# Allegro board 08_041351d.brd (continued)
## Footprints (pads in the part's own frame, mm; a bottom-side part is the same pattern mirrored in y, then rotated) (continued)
C0201
  rect 0.305x0.406 smd: 1(-0.318,0) 2(0.318,0)
C0402
  rect 0.889x0.813 smd: 1(-0.635,0) 2(0.635,0)
C0402H22
  rect 0.889x0.813 smd: 1(-0.635,0) 2(0.635,0)
C0603
  rect 1.092x1.194 smd: 1(-0.851,0) 2(0.851,0)
C0805
  rect 1.295x1.6 smd: 1(-0.953,0) 2(0.953,0)
C0805H53
  rect 1.295x1.6 smd: 1(-0.953,0) 2(0.953,0)
C0805H60
  rect 1.295x1.6 smd: 1(-0.953,0) 2(0.953,0)
C1206H71
  rect 1.6x2.007 smd: 1(-1.397,0) 2(1.397,0)
CNFCI61082-101400
  round 2.21 hole 1.194 unplated: (-22.1,0)
  round 1.905 hole 0.787 unplated: (22.1,0)
  rect 0.508x2.007 smd: 1(-19.6,-2.2) 2(-19.6,2.2) 3(-18.8,-2.2) 4(-18.8,2.2) 5(-18,-2.2) 6(-18,2.2) 7(-17.2,-2.2) 8(-17.2,2.2) 9(-16.4,-2.2) 10(-16.4,2.2) 11(-15.6,-2.2) 12(-15.6,2.2) 13(-14.8,-2.2) 14(-14.8,2.2) 15(-14,-2.2) 16(-14,2.2) 17(-13.2,-2.2) 18(-13.2,2.2) 19(-12.4,-2.2) 20(-12.4,2.2) 21(-11.6,-2.2) 22(-11.6,2.2) 23(-10.8,-2.2) 24(-10.8,2.2) 25(-10,-2.2) 26(-10,2.2) 27(-9.2,-2.2) 28(-9.2,2.2) 29(-8.4,-2.2) 30(-8.4,2.2) 31(-7.6,-2.2) 32(-7.6,2.2) 33(-6.8,-2.2) 34(-6.8,2.2) 35(-6,-2.2) 36(-6,2.2) 37(-5.2,-2.2) 38(-5.2,2.2) 39(-4.4,-2.2) 40(-4.4,2.2) 41(-3.6,-2.2) 42(-3.6,2.2) 43(-2.8,-2.2) 44(-2.8,2.2) 45(-2,-2.2) 46(-2,2.2) 47(-1.2,-2.2) 48(-1.2,2.2) 49(-0.4,-2.2) 50(-0.4,2.2) 51(0.4,-2.2) 52(0.4,2.2) 53(1.2,-2.2) 54(1.2,2.2) 55(2,-2.2) 56(2,2.2) 57(2.8,-2.2) 58(2.8,2.2) 59(3.6,-2.2) 60(3.6,2.2) 61(4.4,-2.2) 62(4.4,2.2) 63(5.2,-2.2) 64(5.2,2.2) 65(6,-2.2) 66(6,2.2) 67(6.8,-2.2) 68(6.8,2.2) 69(7.6,-2.2) 70(7.6,2.2) 71(8.4,-2.2) 72(8.4,2.2) 73(9.2,-2.2) 74(9.2,2.2) 75(10,-2.2) 76(10,2.2) 77(10.8,-2.2) 78(10.8,2.2) 79(11.6,-2.2) 80(11.6,2.2) 81(12.4,-2.2) 82(12.4,2.2) 83(13.2,-2.2) 84(13.2,2.2) 85(14,-2.2) 86(14,2.2) 87(14.8,-2.2) 88(14.8,2.2) 89(15.6,-2.2) 90(15.6,2.2) 91(16.4,-2.2) 92(16.4,2.2) 93(17.2,-2.2) 94(17.2,2.2) 95(18,-2.2) 96(18,2.2) 97(18.8,-2.2) 98(18.8,2.2) 99(19.6,-2.2) 100(19.6,2.2)
CNHIROSE-U_FL-R-SMT-1
  rect 0.635x1.041 smd: 1(0,-1.521)
  rect 1.041x2.21 smd: 2(-1.471,0) 3(1.471,0)
CNHIROSEDM3CS-SF
  rect 2.007x0.711 smd: 1(-6.204,-3.2) 2(-6.204,-2.1) 3(-6.204,-1) 4(-6.204,0.1) 5(-6.204,1.2) 6(-6.204,2.3) 7(-6.204,3.4) 8(-6.204,4.5)
  rect 1.397x2.692 smd: 9(6.5,-1.8) GND3(6.5,3.1)
  rect 2.591x1.499 smd: GND1(-5.7,-6.75)
  rect 1.194x1.194 smd: GND2(6.6,-4.85)
  rect 2.591x0.991 smd: GND4(-5.7,6.6)
DFN8_3X3_PAD2_38X1_64
  oval 0.305x0.838 smd: 1(-0.75,-1.45) 2(-0.25,-1.45) 3(0.25,-1.45) 4(0.75,-1.45) 5(0.75,1.45) 6(0.25,1.45) 7(-0.25,1.45) 8(-0.75,1.45)
  rect 2.388x1.651 smd: PAD(0,0)
DQFN14_3X2_5_PAD1_65X1_15
  oval 0.914x0.254 smd: 1(-1.557,-0.25) 7(1.557,-0.25) 8(1.557,0.25) 14(-1.557,0.25)
  oval 0.254x0.914 smd: 2(-1,-1.307) 3(-0.5,-1.307) 4(0,-1.307) 5(0.5,-1.307) 6(1,-1.307) 9(1,1.307) 10(0.5,1.307) 11(0,1.307) 12(-0.5,1.307) 13(-1,1.307)
  rect 1.651x1.143 smd: PAD(0,0)
FBGA96_C
  round 0.356 smd: A1(-6,-3.2) A2(-6,-2.4) A3(-6,-1.6) A7(-6,1.6) A8(-6,2.4) A9(-6,3.2) B1(-5.2,-3.2) B2(-5.2,-2.4) B3(-5.2,-1.6) B7(-5.2,1.6) B8(-5.2,2.4) B9(-5.2,3.2) C1(-4.4,-3.2) C2(-4.4,-2.4) C3(-4.4,-1.6) C7(-4.4,1.6) C8(-4.4,2.4) C9(-4.4,3.2) D1(-3.6,-3.2) D2(-3.6,-2.4) D3(-3.6,-1.6) D7(-3.6,1.6) D8(-3.6,2.4) D9(-3.6,3.2) E1(-2.8,-3.2) E2(-2.8,-2.4) E3(-2.8,-1.6) E7(-2.8,1.6) E8(-2.8,2.4) E9(-2.8,3.2) F1(-2,-3.2) F2(-2,-2.4) F3(-2,-1.6) F7(-2,1.6) F8(-2,2.4) F9(-2,3.2) G1(-1.2,-3.2) G2(-1.2,-2.4) G3(-1.2,-1.6) G7(-1.2,1.6) G8(-1.2,2.4) G9(-1.2,3.2) H1(-0.4,-3.2) H2(-0.4,-2.4) H3(-0.4,-1.6) H7(-0.4,1.6) H8(-0.4,2.4) H9(-0.4,3.2) J1(0.4,-3.2) J2(0.4,-2.4) J3(0.4,-1.6) J7(0.4,1.6) J8(0.4,2.4) J9(0.4,3.2) K1(1.2,-3.2) K2(1.2,-2.4) K3(1.2,-1.6) K7(1.2,1.6) K8(1.2,2.4) K9(1.2,3.2) L1(2,-3.2) L2(2,-2.4) L3(2,-1.6) L7(2,1.6) L8(2,2.4) L9(2,3.2) M1(2.8,-3.2) M2(2.8,-2.4) M3(2.8,-1.6) M7(2.8,1.6) M8(2.8,2.4) M9(2.8,3.2) N1(3.6,-3.2) N2(3.6,-2.4) N3(3.6,-1.6) N7(3.6,1.6) N8(3.6,2.4) N9(3.6,3.2) P1(4.4,-3.2) P2(4.4,-2.4) P3(4.4,-1.6) P7(4.4,1.6) P8(4.4,2.4) P9(4.4,3.2) R1(5.2,-3.2) R2(5.2,-2.4) R3(5.2,-1.6) R7(5.2,1.6) R8(5.2,2.4) R9(5.2,3.2) T1(6,-3.2) T2(6,-2.4) T3(6,-1.6) T7(6,1.6) T8(6,2.4) T9(6,3.2)
JPRSLD03
  rect 0.61x1.524 smd: 1(-0.838,0) 2(0,0) 3(0.838,0)
L0402
  rect 0.889x0.813 smd: 1(-0.635,0) 2(0.635,0)
L0402#2
  rect 0.483x0.61 smd: 1(-0.43,0) 2(0.43,0)
L0603
  rect 0.889x0.813 smd: 1(-0.737,0) 2(0.737,0)
L0805
  rect 1.143x1.27 smd: 1(-0.953,0) 2(0.953,0)
L1008_A
  rect 0.889x2.54 smd: 1(-1.206,0) 2(1.206,0)
L1210H67
  rect 1.245x2.007 smd: 1(-1.272,0) 2(1.272,0)
LED0603
  rect 0.965x0.762 smd: A(0.8,0) C(-0.8,0)
LSMSQ79H41
  rect 1.041x2.21 smd: 1(-0.724,0) 2(0.724,0)
LSMSQ157H83
  rect 1.473x3.683 smd: 1(-1.232,0) 2(1.232,0)
MLT15CCC2243A
  rect 3.15x1.016 smd: GND1(-11.455,-13.538) GND2(-5.867,-13.538) GND3(-0.279,-13.538) GND4(5.309,-13.538) GND5(10.897,-13.538) GND11(10.897,13.538) GND12(5.309,13.538) GND13(-0.279,13.538) GND14(-5.867,13.538) GND15(-11.455,13.538)
  rect 1.016x3.15 smd: GND6(14.148,-9.728) GND7(14.148,-5.029) GND8(14.148,-0.33) GND9(14.148,4.369) GND10(14.148,9.068) GND16(-14.148,7.925) GND17(-14.148,0) GND18(-14.148,-7.925)
  rect 4.572x1.016 smd: GND19(-10.135,0)
  rect 1.016x1.88 smd: GND20(-5.867,5.486) GND22(-5.867,-6.756)
  rect 1.016x4.572 smd: GND21(-5.867,0)
MSOP8
  rect 0.305x1.321 smd: 1(-0.975,-2.3) 2(-0.325,-2.3) 3(0.325,-2.3) 4(0.975,-2.3) 5(0.975,2.3) 6(0.325,2.3) 7(-0.325,2.3) 8(-0.975,2.3)
QFN8_3X3_PAD2_44X1_7
  oval 0.305x0.914 smd: 1(-0.75,-1.557) 2(-0.25,-1.557) 3(0.25,-1.557) 4(0.75,-1.557) 5(0.75,1.557) 6(0.25,1.557) 7(-0.25,1.557) 8(-0.75,1.557)
  rect 2.438x1.702 smd: PAD(0,0)
QFN10_1_6X1_3
  oval 0.61x0.203 smd: 1(-0.8,-0.4) 4(0.8,-0.4) 5(0.8,0) 6(0.8,0.4) 9(-0.8,0.4) 10(-0.8,0)
  oval 0.203x0.813 smd: 2(-0.2,-0.65) 3(0.2,-0.65) 7(0.2,0.65) 8(-0.2,0.65)
QFN16_4X4_PAD2_1X2_1
  oval 0.356x1.041 smd: 1(-0.975,-1.9) 2(-0.325,-1.9) 3(0.325,-1.9) 4(0.975,-1.9) 9(0.975,1.9) 10(0.325,1.9) 11(-0.325,1.9) 12(-0.975,1.9)
  oval 1.041x0.356 smd: 5(1.9,-0.975) 6(1.9,-0.325) 7(1.9,0.325) 8(1.9,0.975) 13(-1.9,0.975) 14(-1.9,0.325) 15(-1.9,-0.325) 16(-1.9,-0.975)
  rect 2.108x2.108 smd: PAD(0,0)
QFN16_4X4_PAD2_5X2_5
  oval 0.356x0.991 smd: 1(-0.975,-1.974) 2(-0.325,-1.974) 3(0.325,-1.974) 4(0.975,-1.974) 9(0.975,1.974) 10(0.325,1.974) 11(-0.325,1.974) 12(-0.975,1.974)
  oval 0.991x0.356 smd: 5(1.974,-0.975) 6(1.974,-0.325) 7(1.974,0.325) 8(1.974,0.975) 13(-1.974,0.975) 14(-1.974,0.325) 15(-1.974,-0.325) 16(-1.974,-0.975)
  rect 2.489x2.489 smd: PAD(0,0)
QFN20_4X4_PAD2_6X2_6
  oval 0.305x1.041 smd: 1(-1,-2.019) 2(-0.5,-2.019) 3(0,-2.019) 4(0.5,-2.019) 5(1,-2.019) 11(1,2.019) 12(0.5,2.019) 13(0,2.019) 14(-0.5,2.019) 15(-1,2.019)
  oval 1.041x0.305 smd: 6(2.019,-1) 7(2.019,-0.5) 8(2.019,0) 9(2.019,0.5) 10(2.019,1) 16(-2.019,1) 17(-2.019,0.5) 18(-2.019,0) 19(-2.019,-0.5) 20(-2.019,-1)
  rect 2.591x2.591 smd: PAD(0,0)
QFN24_4X4_PAD2_5X2_5
  oval 0.305x0.991 smd: 1(-1.25,-2) 2(-0.75,-2) 3(-0.25,-2) 4(0.25,-2) 5(0.75,-2) 6(1.25,-2) 13(1.25,2) 14(0.75,2) 15(0.25,2) 16(-0.25,2) 17(-0.75,2) 18(-1.25,2)
  oval 0.991x0.305 smd: 7(2,-1.25) 8(2,-0.75) 9(2,-0.25) 10(2,0.25) 11(2,0.75) 12(2,1.25) 19(-2,1.25) 20(-2,0.75) 21(-2,0.25) 22(-2,-0.25) 23(-2,-0.75) 24(-2,-1.25)
  rect 2.489x2.489 smd: PAD(0,0)
QFN32_5X5_PAD3_1X3_1
  oval 0.305x0.889 smd: 1(-1.75,-2.45) 2(-1.25,-2.45) 3(-0.75,-2.45) 4(-0.25,-2.45) 5(0.25,-2.45) 6(0.75,-2.45) 7(1.25,-2.45) 8(1.75,-2.45) 17(1.75,2.45) 18(1.25,2.45) 19(0.75,2.45) 20(0.25,2.45) 21(-0.25,2.45) 22(-0.75,2.45) 23(-1.25,2.45) 24(-1.75,2.45)
  oval 0.889x0.305 smd: 9(2.45,-1.75) 10(2.45,-1.25) 11(2.45,-0.75) 12(2.45,-0.25) 13(2.45,0.25) 14(2.45,0.75) 15(2.45,1.25) 16(2.45,1.75) 25(-2.45,1.75) 26(-2.45,1.25) 27(-2.45,0.75) 28(-2.45,0.25) 29(-2.45,-0.25) 30(-2.45,-0.75) 31(-2.45,-1.25) 32(-2.45,-1.75)
  rect 3.099x3.099 smd: PAD(0,0)
QFN32_5X5_PAD3_3X3_3
  oval 0.305x0.889 smd: 1(-1.75,-2.45) 2(-1.25,-2.45) 3(-0.75,-2.45) 4(-0.25,-2.45) 5(0.25,-2.45) 6(0.75,-2.45) 7(1.25,-2.45) 8(1.75,-2.45) 17(1.75,2.45) 18(1.25,2.45) 19(0.75,2.45) 20(0.25,2.45) 21(-0.25,2.45) 22(-0.75,2.45) 23(-1.25,2.45) 24(-1.75,2.45)
  oval 0.889x0.305 smd: 9(2.45,-1.75) 10(2.45,-1.25) 11(2.45,-0.75) 12(2.45,-0.25) 13(2.45,0.25) 14(2.45,0.75) 15(2.45,1.25) 16(2.45,1.75) 25(-2.45,1.75) 26(-2.45,1.25) 27(-2.45,0.75) 28(-2.45,0.25) 29(-2.45,-0.25) 30(-2.45,-0.75) 31(-2.45,-1.25) 32(-2.45,-1.75)
  rect 3.302x3.302 smd: PAD(0,0)
QFN56_8X8_PAD4_37X4_37
  oval 0.305x0.838 smd: 1(-3.25,-3.95) 2(-2.75,-3.95) 3(-2.25,-3.95) 4(-1.75,-3.95) 5(-1.25,-3.95) 6(-0.75,-3.95) 7(-0.25,-3.95) 8(0.25,-3.95) 9(0.75,-3.95) 10(1.25,-3.95) 11(1.75,-3.95) 12(2.25,-3.95) 13(2.75,-3.95) 14(3.25,-3.95) 29(3.25,3.95) 30(2.75,3.95) 31(2.25,3.95) 32(1.75,3.95) 33(1.25,3.95) 34(0.75,3.95) 35(0.25,3.95) 36(-0.25,3.95) 37(-0.75,3.95) 38(-1.25,3.95) 39(-1.75,3.95) 40(-2.25,3.95) 41(-2.75,3.95) 42(-3.25,3.95)
  oval 0.838x0.305 smd: 15(3.95,-3.25) 16(3.95,-2.75) 17(3.95,-2.25) 18(3.95,-1.75) 19(3.95,-1.25) 20(3.95,-0.75) 21(3.95,-0.25) 22(3.95,0.25) 23(3.95,0.75) 24(3.95,1.25) 25(3.95,1.75) 26(3.95,2.25) 27(3.95,2.75) 28(3.95,3.25) 43(-3.95,3.25) 44(-3.95,2.75) 45(-3.95,2.25) 46(-3.95,1.75) 47(-3.95,1.25) 48(-3.95,0.75) 49(-3.95,0.25) 50(-3.95,-0.25) 51(-3.95,-0.75) 52(-3.95,-1.25) 53(-3.95,-1.75) 54(-3.95,-2.25) 55(-3.95,-2.75) 56(-3.95,-3.25)
  rect 4.369x4.369 smd: PAD(0,0)
R0201
  rect 0.305x0.406 smd: 1(-0.318,0) 2(0.318,0)
R0402
  rect 0.889x0.813 smd: 1(-0.635,0) 2(0.635,0)
R0603
  rect 1.092x1.194 smd: 1(-0.851,0) 2(0.851,0)
SON10_2X2_PAD1_5X0_9
  oval 0.203x0.762 smd: 1(-0.8,-1) 2(-0.4,-1) 3(0,-1) 4(0.4,-1) 5(0.8,-1) 6(0.8,1) 7(0.4,1) 8(0,1) 9(-0.4,1) 10(-0.8,1)
  rect 1.499x0.889 smd: PAD(0,0)
SOT23
  rect 1.016x1.397 smd: 1(-0.94,-1.118) 2(0.94,-1.118) 3(0,1.118)
SOT23_6-2
  rect 0.711x0.991 smd: 1(-0.95,-1.2) 2(0,-1.2) 3(0.95,-1.2) 4(0.95,1.2) 5(0,1.2) 6(-0.95,1.2)
SWSML213W98H98
  rect 0.991x1.295 smd: 1(-1.75,-1.948) 2(0,1.948) 3(1.75,-1.948)
SWSMSQ197H165
  rect 1.778x1.27 smd: 1A(-1.905,-1.27) 1B(1.905,-1.27) 2A(-1.905,1.27) 2B(1.905,1.27)
TBGA24
  round 0.33 smd: A2(-2,-1) A3(-2,0) A4(-2,1) A5(-2,2) B1(-1,-2) B2(-1,-1) B3(-1,0) B4(-1,1) B5(-1,2) C1(0,-2) C2(0,-1) C3(0,0) C4(0,1) C5(0,2) D1(1,-2) D2(1,-1) D3(1,0) D4(1,1) D5(1,2) E1(2,-2) E2(2,-1) E3(2,0) E4(2,1) E5(2,2)
TPC75D45
  round 1.905 hole 1.143: 1(0,0)
TPSMC30
  round 0.762 smd: 1(0,0)
TSML150W160H160
  rect 0.762x1.651 smd: 1(-1.27,1.587) 2(0,1.587) 3(1.27,1.587) 4(1.27,-1.587) 5(0,-1.587) 6(-1.27,-1.587)
TSOT-5
  rect 0.508x1.524 smd: 1(-0.95,-1.17) 2(0,-1.17) 3(0.95,-1.17) 4(0.95,1.17) 5(-0.95,1.17)
unnamed#2
  round 1.016 smd: (0,0)
YSML98W79H35
  rect 1.092x0.991 smd: 1(-0.921,-0.72) 2(0.921,-0.72) 3(0.921,0.72) 4(-0.921,0.72)
YSML126W98H39
  rect 1.397x1.194 smd: 1(-1.199,-0.847) 2(1.199,-0.847) 3(1.199,0.847) 4(-1.199,0.847)
YSML126W98H47
  rect 1.397x1.194 smd: 1(-1.2,-0.95) 2(1.2,-0.95) 3(1.2,0.95) 4(-1.2,0.95)

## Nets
1.0V: C128.1 C130.1 C131.1 E4.1 E5.1 E6.1 L6.2(N2) R49.2(N2)
1.8V: C129.1 C135.1 C148.1 C149.1 E9.1 E14.1 L10.2(N2) R22.2(N2) R39.1 U19.1 U19.2 U19.3 U19.4 U19.15 U19.16 U20.1 U20.2 U20.3 U20.4 U20.15 U20.16
1.35V: C132.1 C136.1 E2.1 E3.1 L7.2(N2) R35.2(N2)
3.3V: C38.1 C111.2(N2) C124.1 C134.1 C152.1 C188.2(N2) C199.1 C244.2(N2) D3.A(P) E7.1 E8.1 E15.1 E16.1 R33.1 R42.1 R43.1 R44.1 R61.1 R63.1 R65.1 U5.6(VDD) U6.5 U6.8 U7.1 U7.3 U9.1(VOUT) U9.2 U21.8(VCCB) U24.10 U24.16 U24.17
GND: C1.2(N2) C2.2(N2) C3.2(N2) C4.2(N2) C5.2(N2) C7.2(N2) C10.2(N2) C11.2(N2) C12.1 C13.1 C14.1 C15.2(N2) C16.2(N2) C17.2(N2) C18.2(N2) C19.2(N2) C20.2(N2) C21.2(N2) C22.2(N2) C23.2(N2) C24.1 C27.2(N2) C28.2(N2) C29.2(N2) C30.2(N2) C31.2(N2) C32.2(N2) C33.2(N2) C34.2(N2) C35.2(N2) C36.2(N2) C37.2(N2) C38.2(N2) C39.2(N2) C40.2(N2) C41.2(N2) C42.2(N2) C43.1 C44.2(N2) C45.2(N2) C46.2(N2) C47.2(N2) C48.2(N2) C49.2(N2) C50.2(N2) C51.2(N2) C52.2(N2) C53.2(N2) C54.2(N2) C55.2(N2) C56.2(N2) C57.2(N2) C58.2(N2) C59.2(N2) C60.2(N2) C61.2(N2) C63.2(N2) C64.2(N2) C65.2(N2) C66.2(N2) C67.2(N2) C68.2(N2) C69.2(N2) C70.2(N2) C71.2(N2) C72.2(N2) C73.2(N2) C74.2(N2) C75.2(N2) C76.2(N2) C77.2(N2) C78.2(N2) C79.2(N2) C80.2(N2) C81.2(N2) C82.2(N2) C83.2(N2) C84.2(N2) C86.2(N2) C87.2(N2) C88.2(N2) C89.2(N2) C91.2(N2) C92.2(N2) C93.1 C94.2(N2) C95.2(N2) C96.2(N2) C97.2(N2) C98.2(N2) C100.2(N2) C101.2(N2) C102.2(N2) C103.2(N2) C104.1 C105.1 C106.2(N2) C107.2(N2) C108.2(N2) C109.2(N2) C111.1 C112.2(N2) C113.2(N2) C115.2(N2) C116.2(N2) C117.2(N2) C118.2(N2) C119.2(N2) C120.2(N2) C121.2(N2) C122.1 C123.1 C124.2(N2) C125.2(N2) C126.2(N2) C128.2(N2) C129.2(N2) C130.2(N2) C131.2(N2) C132.2(N2) C133.2(N2) C134.2(N2) C135.2(N2) C136.2(N2) C137.2(N2) C138.2(N2) C139.2(N2) C140.2(N2) C141.2(N2) C142.1 C143.2(N2) C144.1 C145.1 C146.2(N2) C147.2(N2) C148.2(N2) C149.2(N2) C150.2(N2) C151.2(N2) C152.2(N2) C158.2(N2) C159.2(N2) C162.2(N2) C163.2(N2) C165.2(N2) C167.2(N2) C169.2(N2) C170.2(N2) C171.2(N2) C173.2(N2) C174.2(N2) C175.2(N2) C178.2(N2) C179.2(N2) C181.2(N2) C182.2(N2) C183.2(N2) C184.2(N2) C188.1 C191.2(N2) C193.2(N2) C194.2(N2) C195.2(N2) C196.2(N2) C197.2(N2) C198.2(N2) C199.2(N2) C200.2(N2) C201.2(N2) C203.2(N2) C206.2(N2) C208.2(N2) C210.2(N2) C211.2(N2) C212.2(N2) C214.2(N2) C217.2(N2) C218.2(N2) C219.2(N2) C224.2(N2) C225.2(N2) C226.2(N2) C243.1 C244.1 C245.2(N2) C246.2(N2) C251.2(N2) C311.2(N2) C312.2(N2) C313.2(N2) C314.2(N2) C315.2(N2) C319.2(N2) C320.2(N2) C321.2(N2) C322.2(N2) C323.2(N2) C324.2(N2) C325.2(N2) C326.2(N2) C327.2(N2) C328.2(N2) C329.2(N2) C330.2(N2) C331.2(N2) C332.2(N2) C333.2(N2) C334.2(N2) C335.2(N2) C340.2(N2) C341.2(N2) C342.2(N2) C343.2(N2) C344.2(N2) C354.2(N2) C355.2(N2) C356.2(N2) C357.2(N2) C358.2(N2) C360.2(N2) C361.2(N2) C363.2(N2) C364.2(N2) C365.2(N2) E12.1 J3.6 J3.GND1 J3.GND2 J3.GND3 J3.GND4 JX1.15 JX1.16 JX1.21 JX1.22 JX1.27 JX1.28 JX1.33 JX1.34 JX1.39 JX1.40 JX1.45 JX1.46 JX1.51 JX1.52 JX1.65 JX1.66 JX1.71 JX1.72 JX1.77 JX1.85 JX1.86 JX1.95 JX1.96 JX2.15 JX2.16 JX2.21 JX2.22 JX2.27 JX2.28 JX2.33 JX2.34 JX2.39 JX2.40 JX2.45 JX2.46 JX2.51 JX2.52 JX2.65 JX2.66 JX2.71 JX2.72 JX2.77 JX2.85 JX2.86 JX2.91 JX2.92 JX3.6 JX3.12 JX3.17 JX3.18 JX3.23 JX3.24 JX3.29 JX3.35 JX3.40 JX3.49 JX3.50 JX3.55 JX3.56 JX3.61 JX3.62 JX3.65 JX3.71 JX3.72 JX3.77 JX3.78 JX3.83 JX3.84 JX3.89 JX3.90 JX3.95 JX3.96 JX4.5 JX4.6 JX4.11 JX4.12 JX4.17 JX4.18 JX4.23 JX4.24 JX4.29 JX4.30 JX4.39 JX4.40 JX4.49 JX4.50 JX4.55 JX4.56 JX4.61 JX4.62 JX4.65 JX4.66 JX4.71 JX4.72 JX4.83 JX4.84 JX4.89 JX4.90 JX4.95 JX4.96 M1.GND1 M1.GND2 M1.GND3 M1.GND4 M1.GND5 M1.GND6 M1.GND7 M1.GND8 M1.GND9 M1.GND10 M1.GND11 M1.GND12 M1.GND13 M1.GND14 M1.GND15 M1.GND16 M1.GND17 M1.GND18 M1.GND19 M1.GND20 M1.GND21 M1.GND22 Q1.2(S) Q2.2(S) Q3.2(S) Q4.2(S) Q6.2(S) Q14.2(S) R5.2(N2) R10.1 R12.1 R13.2(N2) R14.2(N2) R20.1 R26.2(N2) R27.2(N2) R29.1 R34.2(N2) R38.2(N2) R41.2(N2) R45.2(N2) R47.2(N2) R50.2(N2) R53.2(N2) R59.2(N2) R62.2(N2) R64.2(N2) R66.2(N2) R68.2(N2) R101.2(N2) R111.1 R116.2(N2) R119.2(N2) R120.2(N2) R125.2(N2) R133.2(N2) R135.2(N2) R165.2(N2) R166.2(N2) R176.2(N2) R191.2(N2) RXA.2 RXA.3(SH2) RXB.2 RXB.3(SH2) S1.1(NO) S3.1(NO) S4.1(NO) SW1.2A SW1.2B(N4) T1.1 T1.2 T1.5 T2.1 T2.2 T2.5 T3.1 T3.2 T3.5 T4.1 T4.2 T4.5 TXA.2 TXA.3(SH2) TXB.2 TXB.3(SH2) TXM.2 TXM.3(SH2) U1.A8 U1.A18 U1.B1 U1.B11 U1.C4 U1.C9 U1.C14 U1.D17 U1.E10 U1.E20 U1.F3 U1.F7 U1.F10 U1.G10 U1.G12 U1.G16 U1.H7 U1.H9 U1.H11 U1.H13 U1.H19 U1.J2 U1.J8 U1.J12 U1.K5 U1.K7 U1.K11 U1.K13 U1.K15 U1.L8 U1.L12 U1.L18 U1.M1 U1.M7 U1.M11 U1.M13 U1.N4 U1.N8 U1.N10 U1.N12 U1.N14 U1.P7 U1.P9 U1.P11 U1.P13 U1.P17 U1.R8 U1.R12 U1.R20 U1.T3 U1.T7 U1.T13 U1.U6 U1.U16 U1.V9 U1.V19 U1.W2 U1.W12 U1.Y5 U1.Y15 U2.A9 U2.B1 U2.B3 U2.B9 U2.D1 U2.D8 U2.E1 U2.E2 U2.E8 U2.F9 U2.G1 U2.G8 U2.G9 U2.J2 U2.J8 U2.M1 U2.M9 U2.P1 U2.P9 U2.T1 U2.T9 U3.A9 U3.B1 U3.B3 U3.B9 U3.D1 U3.D8 U3.E1 U3.E2 U3.E8 U3.F9 U3.G1 U3.G8 U3.G9 U3.J2 U3.J8 U3.M1 U3.M9 U3.P1 U3.P9 U3.T1 U3.T9 U4.1 U4.19 U4.20 U4.21 U4.22 U4.PAD U5.10 U6.3 U6.6 U6.PAD U7.2 U9.3 U9.6 U9.PAD U10.PAD U11.2 U11.11 U11.PAD U13.B3 U14.4 U14.8 U14.PAD U15.PAD U16.5(REF2) U17.A1 U17.A2 U17.A4 U17.A5 U17.A6 U17.A12 U17.B1 U17.B2 U17.B12 U17.C1 U17.C2 U17.C4 U17.C7 U17.C8 U17.C9 U17.C10 U17.C11 U17.C12 U17.D1 U17.D12 U17.E1 U17.F1 U17.F3 U17.F7 U17.F9 U17.F11 U17.G12 U17.H2 U17.H3 U17.H6 U17.H7 U17.H10 U17.J2 U17.K1 U17.K2 U17.K12 U17.L1 U17.L2 U17.L3 U17.L7 U17.L8 U17.L9 U17.L10 U17.L11 U17.L12 U17.M4 U17.M6 U18.5 U18.6 U18.7 U18.8 U18.PAD U19.6 U19.PAD U20.6 U20.PAD U21.4 U22.7 U22.8 U22.9 U22.PAD U24.6 U24.9 U24.PAD Y1.2 Y2.2 Y2.4 Y3.2 Y4.2
VCC-1P35: C86.1 C87.1 C88.1 C89.1 C91.1 C92.1 C94.1 C95.1 C96.1 C97.1 C100.1 C106.1 C107.1 C108.1 C109.1 C112.1 C115.1 C116.1 C117.1 C118.1 C120.1 C147.1 E3.2(N2) R134.2(N2) U2.A1 U2.A8 U2.B2 U2.C1 U2.C9 U2.D2 U2.D9 U2.E9 U2.F1 U2.G7 U2.H2 U2.H9 U2.K2 U2.K8 U2.N1 U2.N9 U2.R1 U2.R9 U3.A1 U3.A8 U3.B2 U3.C1 U3.C9 U3.D2 U3.D9 U3.E9 U3.F1 U3.G7 U3.H2 U3.H9 U3.K2 U3.K8 U3.N1 U3.N9 U3.R1 U3.R9 U14.1
VCC-3P3V: C43.2(N2) C196.1 E7.2(N2) R178.1 R221.1 R222.1 U14.10
VCC-3P3V-IO: C30.1 C41.1 C42.1 C57.1 C71.1 C184.1 C197.1 D4.A(P) E8.2(N2) J3.4 R4.1 R8.1 R109.1 R167.1 R168.1 R169.2(N2) U1.K6 U1.N6 U1.R6 U1.T6 U11.17(VCCB1) U11.21 U15.20 U15.21
VCC-BRAM: C56.1 C70.1 C72.1 C194.1 E5.2(N2) U1.G11 U1.H10
VCCINT-1P0V: C1.1 C16.1 C19.1 C23.1 C140.1 C141.1 C143.1 C151.1 C195.1 E6.2(N2) U1.G13 U1.H12 U1.J13 U1.K12 U1.L13 U1.M12 U1.N13 U1.P12 U1.R13
VCCO-DDR: C11.1 C17.1 C20.1 C121.1 C125.1 C138.1 C193.1 E2.2(N2) U1.A3 U1.D2 U1.E5 U1.G1 U1.H4 U1.L3 U1.P2 U1.R5 U1.U1 U1.V4
VCCPCOM-1P8V: C24.2(N2) C29.1 C32.1 C39.1 C40.1 C52.1 C53.1 C54.1 C55.1 C82.1 C83.1 C126.1 C145.2(N2) C174.1 C175.1 C179.1 C181.1 C182.1 C183.1 C198.1 E1.1 E9.2(N2) L12.1 Q5.1 R6.1 R7.1 R9.1 R28.1 R31.1 R32.1 R36.1 R37.1 R40.1 R194.1 S1.3 S3.3 S4.3 U1.A13 U1.B6 U1.B16 U1.D7 U1.D12 U1.E15 U1.F8 U1.G9 U1.H8 U1.J11 U1.K8 U1.L11 U1.M8 U1.N9 U1.N11 U1.P10 U1.R9 U11.5 U13.B4 U15.8 U15.11 U15.14 U15.28 U15.30 U15.32 Y1.4(VDD) Y3.4(VDD)
VCCPINT-1P0V: C10.1 C159.1 C162.1 C163.1 C173.1 C191.1 E4.2(N2) U1.G7 U1.J7 U1.L7 U1.N7 U1.P8 U1.R7
VDD_INTERFACE: C28.1 C31.1 C33.1 C35.1 C44.1 C47.1 C51.1 C245.1 C354.1 C355.1 C356.1 C357.1 C363.1 E10.2(N2) R306.2(N2) U1.C19 U1.F18 U1.H14 U1.J17 U1.K20 U1.M16 U17.H12 U22.1
VDDA_GPO: C319.1 C358.1 C360.1 C361.1 E11.2(N2) R67.1 U17.B8
VDDA_GPO_PWR: C200.1 E10.1 E11.1 JX4.9 U6.1(VOUT) U6.2
1P3_SUPPLY_A: C312.1 C313.1 C314.1 C315.1 C320.1 C321.1 C322.1 C323.1 C326.1 C327.1 C328.1 C329.1 U17.B9 U17.B10 U17.E2 U17.F2 U17.J3 U17.K3 U19.9 U19.10 U19.11 U19.12 U19.13 U19.14(VOUT5) U24.18
1P3_SUPPLY_B: C14.2(N2) C21.1 C93.2(N2) C98.1 C324.1 C325.1 C330.1 C331.1 C332.1 C333.1 C334.1 C335.1 C341.1 C342.1 C343.1 C344.1 L1.1 L2.1 L8.1 L9.1 U17.A7 U17.A8 U17.A9 U17.A10 U17.D2 U17.D3 U17.E3 U17.F12 U17.K4 U20.9 U20.10 U20.11 U20.12 U20.13 U20.14(VOUT5) U24.19
AD9364_CLK: C62.1 JX4.63 R5.1
ADP2114_VIN: C146.1 C150.1 R23.2(N2) U4.4 U4.8 U4.10 U4.31
AUXADC: JX4.7 U17.L5
AUXDAC1: JX4.8 U17.B3
AUXDAC2: JX4.10 U17.C3
CARRIER_RESET: JX1.6 Q5.3 R8.2(N2)
COMP_1P8V: C67.1 R46.1 U4.2
COMP_1P35V: C68.1 C114.1 U4.7
CTRL_IN0: U17.C5 U22.2
CTRL_IN1: U17.C6 U22.3
CTRL_IN2: U17.D5 U22.4
CTRL_IN3: U17.D6 U22.5
DDR3_A0: R136.1 U1.N2 U2.N3 U3.N3
DDR3_A1: R137.1 U1.K2 U2.P7 U3.P7
DDR3_A2: R138.1 U1.M3 U2.P3 U3.P3
DDR3_A3: R139.1 U1.K3 U2.N2 U3.N2
DDR3_A4: R140.1 U1.M4 U2.P8 U3.P8
DDR3_A5: R141.1 U1.L1 U2.P2 U3.P2
DDR3_A6: R143.1 U1.L4 U2.R8 U3.R8
DDR3_A7: R144.1 U1.K4 U2.R2 U3.R2
DDR3_A8: R145.1 U1.K1 U2.T8 U3.T8
DDR3_A9: R146.1 U1.J4 U2.R3 U3.R3
DDR3_A10: R147.1 U1.F5 U2.L7 U3.L7
DDR3_A11: R148.1 U1.G4 U2.R7 U3.R7
DDR3_A12: R149.1 U1.E4 U2.N7 U3.N7
DDR3_A13: R150.1 U1.D4 U2.T3 U3.T3
DDR3_A14: R151.1 U1.F4 U2.T7 U3.T7
DDR3_BA0: R152.1 U1.L5 U2.M2 U3.M2
DDR3_BA1: R153.1 U1.R4 U2.N8 U3.N8
DDR3_BA2: R154.1 U1.J5 U2.M3 U3.M3
DDR3_CAS#: R159.1 U1.P5 U2.K3 U3.K3
DDR3_CK_N: R142.2(N2) U1.M2 U2.K7 U3.K7
DDR3_CK_P: R142.1 U1.L2 U2.J7 U3.J7
DDR3_CKE: R160.1 U1.N3 U2.K9 U3.K9
DDR3_CS#: R163.1 U1.N1 U2.L2 U3.L2
DDR3_DM0: U1.A1 U2.E7
DDR3_DM1: U1.F1 U2.D3
DDR3_DM2: U1.T1 U3.E7
DDR3_DM3: U1.Y1 U3.D3
DDR3_DQ0: U1.C3 U2.E3
DDR3_DQ1: U1.B3 U2.F7
DDR3_DQ2: U1.A2 U2.F2
DDR3_DQ3: U1.A4 U2.F8
DDR3_DQ4: U1.D3 U2.H3
DDR3_DQ5: U1.D1 U2.H8
DDR3_DQ6: U1.C1 U2.G2
DDR3_DQ7: U1.E1 U2.H7
DDR3_DQ8: U1.E2 U2.D7
DDR3_DQ9: U1.E3 U2.C3
DDR3_DQ10: U1.G3 U2.C8
DDR3_DQ11: U1.H3 U2.C2
DDR3_DQ12: U1.J3 U2.A7
DDR3_DQ13: U1.H2 U2.A2
DDR3_DQ14: U1.H1 U2.B8
DDR3_DQ15: U1.J1 U2.A3
DDR3_DQ16: U1.P1 U3.E3
DDR3_DQ17: U1.P3 U3.F7
DDR3_DQ18: U1.R3 U3.F2
DDR3_DQ19: U1.R1 U3.F8
DDR3_DQ20: U1.T4 U3.H3
DDR3_DQ21: U1.U4 U3.H8
DDR3_DQ22: U1.U2 U3.G2
DDR3_DQ23: U1.U3 U3.H7
DDR3_DQ24: U1.V1 U3.D7
DDR3_DQ25: U1.Y3 U3.C3
DDR3_DQ26: U1.W1 U3.C8
DDR3_DQ27: U1.Y4 U3.C2
DDR3_DQ28: U1.Y2 U3.A7
DDR3_DQ29: U1.W3 U3.A2
DDR3_DQ30: U1.V2 U3.B8
DDR3_DQ31: U1.V3 U3.A3
DDR3_DQS0_N: U1.B2 U2.G3
DDR3_DQS0_P: U1.C2 U2.F3
DDR3_DQS1_N: U1.F2 U2.B7
DDR3_DQS1_P: U1.G2 U2.C7
DDR3_DQS2_N: U1.T2 U3.G3
DDR3_DQS2_P: U1.R2 U3.F3
DDR3_DQS3_N: U1.W4 U3.B7
DDR3_DQS3_P: U1.W5 U3.C7
DDR3_ODT: R162.1 U1.N5 U2.K1 U3.K1
DDR3_RAS#: R156.1 U1.P4 U2.J3 U3.J3
DDR3_RST#: R133.1 U1.B4 U2.T2 U3.T2
DDR3_WE#: R155.1 U1.M5 U2.L3 U3.L3
DX_0_N: JX1.100 U1.M10
DX_0_P: JX1.98 U1.M9
ETH_MD1_N: JX3.53 U10.27
ETH_MD1_P: JX3.51 U10.28
ETH_MD2_N: JX3.54 U10.23
ETH_MD2_P: JX3.52 U10.24
ETH_MD3_N: JP2.1 U10.21
ETH_MD3_P: JP1.1 U10.22
ETH_MD4_N: JP4.1 U10.17
ETH_MD4_P: JP3.1 U10.18
ETH_PHY_LED0: JX3.47 R18.2(N2)
ETH_PHY_LED1: JX3.48 R17.2(N2)
FB0: R29.2(N2) R48.1 U18.4
FB_1P8V: R39.2(N2) R45.1 U4.32
FB_1P35V: R34.1 R35.1 U4.9
FPGA_DONE: JX1.8 R172.2(N2) U1.R11
FPGA_VBATT: JX1.7 R9.2(N2) U1.F11 U24.20
GPO0: JX4.1 U17.B7
GPO1: JX4.2 U17.B6
GPO2: JX4.3 U17.B5
GPO3: JX4.4 U17.B4
INIT_B_0_JX2_09: JX2.9 R168.2(N2) U1.R10
IO_00_34_AD9364_CLKSEL: Q6.1 R54.1 U1.R19
IO_00_35_AD9364_RST: U1.G14 U17.K5
IO_25_34_JX4: JX4.64 U1.T19
IO_25_35_AD9364_CLKOUT: U1.J15 U17.J6
IO_L01_34_JX4_N: JX4.21 U1.T10
IO_L01_34_JX4_P: JX4.19 U1.T11
IO_L01_35_RX_D0_N: U1.B20 U17.K11
IO_L01_35_RX_D0_P: U1.C20 U17.J12
IO_L02_34_JX4_N: JX4.22 U1.U12
IO_L02_34_JX4_P: JX4.20 U1.T12
IO_L02_35_RX_D1_N: U1.A20 U17.K10
IO_L02_35_RX_D1_P: U1.B19 U17.J11
IO_L03_34_JX4_N: JX4.27 U1.V13
IO_L03_34_JX4_P: JX4.25 R53.1 U1.U13
IO_L03_35_RX_D2_N: U1.D18 U17.K9
IO_L03_35_RX_D2_P: U1.E17 U17.J10
IO_L04_34_JX4_N: JX4.28 U1.W13
IO_L04_34_JX4_P: JX4.26 U1.V12
IO_L04_35_RX_D3_N: U1.D20 U17.K8
IO_L04_35_RX_D3_P: U1.D19 U17.J9
IO_L05_34_JX4_N: JX4.33 U1.T15
IO_L05_34_JX4_P: JX4.31 U1.T14
IO_L05_35_RX_D4_N: U1.E19 U17.K7
IO_L05_35_RX_D4_P: U1.E18 U17.J8
IO_L06_13_JX2_P: JX2.18 U1.V5
IO_L06_34_JX4_N: JX4.34 U1.R14
IO_L06_34_JX4_P: JX4.32 U1.P14
IO_L06_35_RX_D5_N: U1.F17 U17.J7
IO_L06_35_RX_D5_P: U1.F16 U17.H8
IO_L07_34_JX4_N: JX4.37 U1.Y17
IO_L07_34_JX4_P: JX4.35 U1.Y16
IO_L07_35_RX_FRAME_N: U1.M20 U17.G7
IO_L07_35_RX_FRAME_P: U1.M19 U17.G8
IO_L08_34_JX4_N: JX4.38 U1.Y14
IO_L08_34_JX4_P: JX4.36 U1.W14
IO_L08_35_FB_CLK_N: U1.M18 U17.G10
IO_L08_35_FB_CLK_P: U1.M17 U17.F10
IO_L09_34_JX4_N: JX4.43 U1.U17
IO_L09_34_JX4_P: JX4.41 U1.T16
IO_L09_35_TX_FRAME_N: U1.L20 U17.H9
IO_L09_35_TX_FRAME_P: U1.L19 U17.G9
IO_L10_34_JX4_N: JX4.44 U1.W15
IO_L10_34_JX4_P: JX4.42 U1.V15
IO_L10_35_ENABLE: U1.K19 U17.G6
IO_L10_35_SYNC_IN: R111.2(N2) U1.J19 U17.H5
IO_L11_35_EN_AGC: U1.L16 U17.G5
IO_L11_35_TXNRX: U1.L17 U17.H4
IO_L11_SRCC_13_JX2_N: JX2.37 U1.V7
IO_L11_SRCC_13_JX2_P: JX2.35 U1.U7
IO_L11_SRCC_34_JX4_N: JX4.47 U1.U15
IO_L11_SRCC_34_JX4_P: JX4.45 U1.U14
IO_L12_MRCC_13_JX2_N: JX2.38 U1.U10
IO_L12_MRCC_13_JX2_P: JX2.36 U1.T9
IO_L12_MRCC_34_JX4_N: JX4.48 U1.U19
IO_L12_MRCC_34_JX4_P: JX4.46 U1.U18
IO_L12_MRCC_35_DATA_CLK_N: U1.K18 U17.H11
IO_L12_MRCC_35_DATA_CLK_P: U1.K17 U17.G11
IO_L13_35_TX_D0_N: U1.H17 U17.E12
IO_L13_35_TX_D0_P: U1.H16 U17.D11
IO_L13_MRCC_13_JX2_N: JX2.43 U1.Y6
IO_L13_MRCC_13_JX2_P: JX2.41 U1.Y7
IO_L13_MRCC_34_JX4_N: JX4.53 U1.P19
IO_L13_MRCC_34_JX4_P: JX4.51 U1.N18
IO_L14_35_TX_D1_N: U1.H18 U17.E11
IO_L14_35_TX_D1_P: U1.J18 U17.D10
IO_L14_SRCC_13_JX2_N: JX2.44 U1.Y8
IO_L14_SRCC_13_JX2_P: JX2.42 U1.Y9
IO_L14_SRCC_34_JX4_N: JX4.54 U1.P20
IO_L14_SRCC_34_JX4_P: JX4.52 U1.N20
IO_L15_13_JX2_N: JX2.49 U1.W8
IO_L15_13_JX2_P: JX2.47 U1.V8
IO_L15_34_JX4_N: JX4.59 U1.U20
IO_L15_34_JX4_P: JX4.57 U1.T20
IO_L15_35_TX_D2_N: U1.F20 U17.E10
IO_L15_35_TX_D2_P: U1.F19 U17.D9
IO_L16_13_JX2_N: JX2.50 U1.W9
IO_L16_13_JX2_P: JX2.48 U1.W10
IO_L16_34_JX4_N: JX4.60 U1.W20
IO_L16_34_JX4_P: JX4.58 U1.V20
IO_L16_35_TX_D3_N: U1.G18 U17.E9
IO_L16_35_TX_D3_P: U1.G17 U17.D8
IO_L17_13_JX2_N: JX2.55 U1.U8
IO_L17_13_JX2_P: JX2.53 U1.U9
IO_L17_34_JX4_N: JX4.69 U1.Y19
IO_L17_34_JX4_P: JX4.67 U1.Y18
IO_L17_35_TX_D4_N: U1.H20 U17.E8
IO_L17_35_TX_D4_P: U1.J20 U17.D7
IO_L18_13_JX2_N: JX2.56 U1.Y11
IO_L18_13_JX2_P: JX2.54 U1.W11
IO_L18_34_JX4_N: JX4.70 U1.W16
IO_L18_34_JX4_P: JX4.68(N9) U1.V16
IO_L18_35_TX_D5_N: U1.G20 U17.F8
IO_L18_35_TX_D5_P: U1.G19 U17.E7
IO_L19_13_JX2_N: JX2.63 U1.U5
IO_L19_13_JX2_P: JX2.61 U1.T5
IO_L19_34_JX4_N: JX4.75 U1.R17
IO_L19_34_JX4_P: JX4.73 U1.R16
IO_L19_35_CTRL_OUT0: U1.H15 U17.D4
IO_L19_35_CTRL_OUT1: U1.G15 U17.E6
IO_L20_13_JX2_N: JX2.64 U1.Y13
IO_L20_13_JX2_P: JX2.62 U1.Y12
IO_L20_34_JX4_N: JX4.76 U1.R18
IO_L20_34_JX4_P: JX4.74 U1.T17
IO_L20_35_CTRL_OUT2: U1.K14 U17.E5
IO_L20_35_CTRL_OUT3: U1.J14 U17.E4
IO_L21_13_JX2_N: JX2.69 U1.V10
IO_L21_13_JX2_P: JX2.67 U1.V11
IO_L21_34_JX4_N: JX4.79 U1.V18
IO_L21_34_JX4_P: JX4.77 U1.V17
IO_L21_35_CTRL_OUT4: U1.N15 U17.F6
IO_L21_35_CTRL_OUT5: U1.N16 U17.F5
IO_L22_34_JX4_N: JX4.80 U1.W19
IO_L22_34_JX4_P: JX4.78 U1.W18
IO_L22_35_CTRL_OUT6: U1.L14 U17.F4
IO_L22_35_CTRL_OUT7: U1.L15 U17.G4
IO_L23_34_CTRL_IN0: U1.N17 U22.13
IO_L23_34_CTRL_IN1: U1.P18 U22.12
IO_L23_35_SPI_CLK: U1.M15 U17.J5
IO_L23_35_SPI_ENB: U1.M14 U17.K6
IO_L24_34_CTRL_IN2: U1.P15 U22.11
IO_L24_34_CTRL_IN3: U1.P16 U22.10
IO_L24_35_SPI_DI: U1.K16 U17.J4
IO_L24_35_SPI_DO: U1.J16 U17.L6
J3-9: J3.9(N9) R36.2(N2) U5.7
JTAG_TCK: JX1.1 U1.F9
JTAG_TDI: JX1.4 U1.G6
JTAG_TDO: JX1.3 U1.F6
JTAG_TMS: JX1.2 U1.J6
JX3_SD1_CDN: JX3.41 U5.9
JX_VCCO_13: C27.1 C46.1 C48.1 C167.1 C169.1 C170.1 C171.1 C243.2(N2) JX2.98 JX3.45 JX3.46 R57.1 R58.1 U1.T8 U1.U11 U1.W7 U1.Y10 U21.1
JX_VCCO_34: C2.1 C3.1 C4.1 C7.1 C15.1 C18.1 C22.1 C246.1 JX2.78 JX2.79 JX2.80 U1.N19 U1.R15 U1.T18 U1.V14 U1.W17 U1.Y20 U22.14(VCCB)
JX_VIN: C36.1 C37.1 C45.1 C137.1 C139.1 C364.1 C365.1 JX1.57 JX1.58 JX1.59 JX1.60 JX2.12 JX2.57 JX2.58 JX2.59 JX2.60 L302.1 R23.1 R25.2(N2) R56.1 TP2.1(N1) U4.14 U4.15 U4.16(VIN6) U4.25 U4.26 U4.27 U9.8
PG_1P0V: R304.1 U4.28 U18.16
PG_1P8V: JX2.10 R25.1 U4.13 U4.29 U9.5
PG_MODULE: JX2.11 Q14.1 R43.2(N2) U6.7
PHY1_1V8: C74.1 C78.1 C206.1 C212.1 E14.2(N2) R11.1 U10.10 U10.11 U10.49 U10.52
PHY1_AVDD_1V8: C201.1 C203.1 C210.1 C211.1 C218.1 C219.1 R3.1 U10.3 U10.19 U10.26 U10.35 U10.38
PHY1_AVDD_1V8_OUT: R3.2(N2) U10.39 U24.5
PHY1_AVDD_3V3: C49.1 C208.1 C214.1 C217.1 E15.2(N2) U10.20 U10.25
PHY1_DVDD_1V0: C58.1 C63.1 C73.1 C75.1 U10.6 U10.40 U10.42
PHY1_LED_0: Q2.1 R14.1 U10.14
PHY1_LED_1: Q1.1 R13.1 U10.13
PHY1_VDD_3V3: C50.1 C224.1 C225.1 C226.1 E16.2(N2) R15.1 R16.1 U10.36
PS-SRST#: Q5.2(S) R7.2(N2) R19.1 U1.B10
PS_MIO00_500_JX4: JX4.97 U1.E6
PS_MIO01_500_QSPI0_SS_B: R28.2(N2) U1.A7 U13.C2
PS_MIO02_500_QSPI0_IO0: R120.1 U1.B8 U13.D3
PS_MIO03_500_QSPI0_IO1: R119.1 U1.D6 U13.D2
PS_MIO04_500_QSPI0_IO2: R121.1 U1.B7 U13.C4(W#DQ2)
PS_MIO05_500_QSPI0_IO3: R122.1 U1.A6 U13.D4
PS_MIO06_500_QSPI0_SCLK: R116.1 U1.A5 U13.B2
PS_MIO07_500_USB_RESET_B: R31.2(N2) U1.D8 U15.27
PS_MIO08_500_ETH0_RESETN: R32.2(N2) U1.D5 U10.16
PS_MIO09_500_USB_CLK_PD: R27.1 U1.B5 Y3.1
PS_MIO10_500_JX4: JX4.87 U1.E9
PS_MIO11_500_JX4: JX4.88 U1.C6
PS_MIO12_500_JX4: JX4.86 U1.D9
PS_MIO13_500_JX4: JX4.91 U1.E8
PS_MIO14_500_JX4: JX4.93 U1.C5
PS_MIO15_500_JX4: JX4.85 U1.C8
PS_MIO16_501_ETH0_TX_CLK: U1.A19 U10.53
PS_MIO17_501_ETH0_TX_D0: U1.E14 U10.50
PS_MIO18_501_ETH0_TX_D1: U1.B18 U10.51
PS_MIO19_501_ETH0_TX_D2: U1.D10 U10.54
PS_MIO20_501_ETH0_TX_D3: U1.A17 U10.55
PS_MIO21_501_ETH0_TX_CTL: U1.F14 U10.56
PS_MIO22_501_ETH0_RX_CLK: U1.B17 U10.46
PS_MIO23_501_ETH0_RX_D0: U1.D11 U10.44
PS_MIO24_501_ETH0_RX_D1: U1.A16 U10.45
PS_MIO25_501_ETH0_RX_D2: U1.F15 U10.47
PS_MIO26_501_ETH0_RX_D3: U1.A15 U10.48
PS_MIO27_501_ETH0_RX_CTL: U1.D13 U10.43
PS_MIO28_501_USB0_D4: U1.C16 U15.7
PS_MIO29_501_USB0_DIR: U1.C13 U15.31
PS_MIO30_501_USB0_STP: U1.C15 U15.29
PS_MIO31_501_USB0_NXT: U1.E16 U15.2
PS_MIO32_501_USB0_D0: U1.A14 U15.3
PS_MIO33_501_USB0_D1: U1.D15 U15.4
PS_MIO34_501_USB0_D2: U1.A12 U15.5
PS_MIO35_501_USB0_D3: U1.F12 U15.6
PS_MIO36_501_USB0_CLK: U1.A11 U15.1
PS_MIO37_501_USB0_D5: U1.A10 U15.9
PS_MIO38_501_USB0_D6: U1.E13 U15.10
PS_MIO39_501_USB0_D7: U1.C18 U15.13
PS_MIO40_501_SD0_CLK: U1.D14 U11.9
PS_MIO41_501_SD0_CMD: U1.C17 U11.4
PS_MIO42_501_SD0_DATA0: U1.E12 U11.6
PS_MIO43_501_SD0_DATA1: U1.A9 U11.7
PS_MIO44_501_SD0_DATA2: U1.F13 U11.1
PS_MIO45_501_SD0_DATA3: U1.B15 U11.3
PS_MIO46_501_JX4: JX4.92 R37.2(N2) U1.D16
PS_MIO47_501_JX4: JX4.94 R26.1 U1.B14
PS_MIO48_501_JX4: JX4.99 U1.B12
PS_MIO49_501_JX4: JX4.98 U1.C12
PS_MIO50_501_SD0_CD: U1.B13 U5.8
PS_MIO51_501_JX4: JX4.100 U1.B9
PS_MIO52_501_ETH0_MDC: U1.C10 U10.7
PS_MIO53_501_ETH0_MDIO: R11.2(N2) U1.C11 U10.8
PWR_ENABLE: JX1.5 R56.2(N2) U18.15
PWR_GD: R306.1 U9.7 U19.5 U20.5
PWR_GD_1.35V: C34.1 R22.1 SW1.1A SW1.1B U1.C7 U4.12
RX_EXT_LO: U17.G1 W1.1(N1)
RX_VCO_LDO_OUT: C13.2(N2) R2.1 U17.G2 U17.G3
RXA_N: C8.2(N2) U17.M2
RXA_P: C9.2(N2) U17.M1
RXB_N: C85.2(N2) U17.J1
RXB_P: C90.2(N2) U17.H1
S_IN_N: JP2.3 U10.2
S_IN_P: JP1.3 U10.1
S_OUT_N: JP4.3 U10.5
S_OUT_P: JP3.3 U10.4
SCL: JX2.17 R58.2(N2) U1.W6 U21.2
SCL_AD7291: R44.2(N2) U21.7 U24.15
SD_SEL: S1.2 U5.5 U11.24
SDA: JX2.19 R57.2(N2) U1.V6 U21.3
SDA_AD7291: R42.2(N2) U21.6 U24.14
SDIO_CLKB0: J3.5 U11.19
SDIO_CLKB1: JX3.43 U11.13
SDIO_CMDB0: J3.3 R109.2(N2) U11.20
SDIO_CMDB1: JX3.34 R4.2(N2) U11.12
SDIO_DAT0B0: J3.7 U11.18
SDIO_DAT0B1: JX3.37 U11.14
SDIO_DAT1B0: J3.8 U11.16
SDIO_DAT1B1: JX3.36 U11.15
SDIO_DAT2B0: J3.1 U11.23
SDIO_DAT2B1: JX3.39 U11.8
SDIO_DAT3B0: J3.2 U11.22
SDIO_DAT3B1: JX3.38 U11.10
SYNC: L5.1 U18.9 U18.10 U18.11
TX_MON: C6.2(N2) U17.M5
TX_VCO_1P1V_SUPPLY: C104.2(N2) R123.1 U17.A11 U17.B11
TXA_N: C25.1 L8.2(N2) U17.M8
TXA_P: C26.1 L9.2(N2) U17.M7
TXB_N: C99.1 L1.2(N2) U17.M10
TXB_P: C110.1 L2.2(N2) U17.M9
UNNAMED_2_CAP_I87_N1: C242.1 U10.41
UNNAMED_2_CAP_I87_N2: C242.2(N2) U10.37
UNNAMED_2_CAP_I153_N1: C59.1 U10.33(XTAL_OUT) Y2.1
UNNAMED_2_CAP_I154_N1: C60.1 U10.34 Y2.3(N2)
UNNAMED_2_DIO6PV8_I47_REF1: R178.2(N2) U16.2
UNNAMED_2_IC88E151X_I86_CONFIG: R12.2(N2) U10.15
UNNAMED_2_IC88E151X_I86_RSET: R50.1 U10.30
UNNAMED_2_ICUSB3320C_I42_RBIAS: R176.1 U15.24
UNNAMED_2_ICUSB3320C_I42_REFCLK: R175.1 U15.26
UNNAMED_2_RES_I8_N2: R191.1 R194.2(N2) U1.E11
UNNAMED_2_RES_I50_N2: R175.2(N2) Y3.3
UNNAMED_2_RES_I105_N1: Q4.3 R18.1
UNNAMED_2_RES_I108_N2: Q2.3 Q4.1 R16.2(N2)
UNNAMED_2_RES_I112_N1: Q3.3 R17.1
UNNAMED_2_RES_I114_N2: Q1.3 Q3.1 R15.2(N2)
UNNAMED_3_ICMT25Q_I231_RESET: R19.2(N2) U13.A4
UNNAMED_3_ICXC7Z20_I217_PSCLK50: R114.2(N2) U1.E7
UNNAMED_3_RES_I30_N2: R121.2(N2) S3.2
UNNAMED_3_RES_I33_N2: R122.2(N2) S4.2
UNNAMED_3_RES_I222_N1: R114.1 Y1.3
UNNAMED_3_RES_I228_N2: R40.2(N2) R41.1 Y1.1
UNNAMED_5_ICMT41K256M16_I128_ZQ: R165.1 U2.L8(ZQ)
UNNAMED_5_ICMT41K256M16_I137_ZQ: R166.1 U3.L8(ZQ)
UNNAMED_5_ICTPS51206_I120_S3: R222.2(N2) U14.7
UNNAMED_5_ICTPS51206_I120_S5: R221.2(N2) U14.9
UNNAMED_5_ICTPS51206_I120_VLDOI: R6.2(N2) U14.2
UNNAMED_5_ICTPS51206_I120_VTTSN: R161.2(N2) U14.5(VTTSNS)
UNNAMED_5_ICXC7Z20_I195_PSDDR_2: R135.1 U1.H5
UNNAMED_5_ICXC7Z20_I195_PSDDRVR: R134.1 U1.G5
UNNAMED_6_CAP_I20_N1: C178.1 C251.1 L12.2(N2) U1.G8(VCCPL)
UNNAMED_6_CAP_I222_N1: C189.1 C190.1 E1.2(N2) U1.J9
UNNAMED_6_CAP_I222_N2: C189.2(N2) C190.2(N2) E12.2(N2) U1.J10 U1.K10 U1.L9
UNNAMED_6_DIOLED_I352_N: D4.C R172.1
UNNAMED_6_ICXC7Z20_I344_CFGBVS0: R167.2(N2) U1.M6
UNNAMED_6_ICXC7Z20_I344_PROGRAM: R169.1 U1.L6
UNNAMED_8_AD9364_I22_RBIAS: R125.1 U17.L4
UNNAMED_8_CAP_I135_N1: C8.1 T1.6(SEC_DOT)
UNNAMED_8_CAP_I136_N1: C9.1 T1.4
UNNAMED_8_CAP_I200_N1: C6.1 R1.2(N2)
UNNAMED_8_CAP_I209_N2: C25.2(N2) T2.6(SEC_DOT)
UNNAMED_8_CAP_I210_N2: C26.2(N2) T2.4
UNNAMED_8_CAP_I395_N2: C12.2(N2) R2.2(N2)
UNNAMED_8_CAP_I409_N2: C99.2(N2) T4.6(SEC_DOT)
UNNAMED_8_CAP_I410_N2: C110.2(N2) T4.4
UNNAMED_8_CAP_I416_N1: C85.1 T3.6(SEC_DOT)
UNNAMED_8_CAP_I417_N1: C90.1 T3.4
UNNAMED_8_CAP_I425_N2: C105.2(N2) R123.2(N2)
UNNAMED_8_CNBNC3P_I358_CNTR: RXA.1 T1.3
UNNAMED_8_CNBNC3P_I359_CNTR: T2.3 TXA.1
UNNAMED_8_CNBNC3P_I360_CNTR: R1.1 R101.1 TXM.1
UNNAMED_8_CNBNC3P_I404_CNTR: T4.3 TXB.1
UNNAMED_8_CNBNC3P_I421_CNTR: RXB.1 T3.3
UNNAMED_8_ICFXL4T245_I328_T: R59.1 U22.6
UNNAMED_9_ADP1754_I1076_SS: C311.1 U19.7
UNNAMED_9_ADP1754_I1374_SS: C340.1 U20.7
UNNAMED_9_ADP2114_I1272_FREQ: R10.2(N2) U4.3
UNNAMED_9_ADP2114_I1272_OPCFG: R20.2(N2) U4.6
UNNAMED_9_ADP2114_I1272_SS1: C142.2(N2) U4.30
UNNAMED_9_ADP2114_I1272_SS2: C144.2(N2) U4.11
UNNAMED_9_ADP2114_I1272_SW1: L3.1 U4.23 U4.24
UNNAMED_9_ADP2114_I1272_SW3: L4.1 U4.17 U4.18
UNNAMED_9_ADP2164_I831_PVIN1: C66.1 L302.2(N2) R301.2(N2) R304.2(N2) U18.12 U18.13
UNNAMED_9_ADP2164_I831_RT: R38.1 U18.2
UNNAMED_9_ADP2164_I831_SYNC: C61.1 R301.1 U18.1 U18.3 U18.14(VIN)
UNNAMED_9_CAP_I1364_N1: C64.1 L3.2(N2) L10.1
UNNAMED_9_CAP_I1394_N1: C119.1 C127.1 L5.2(N2) L6.1
UNNAMED_9_CAP_I1398_N2: C127.2(N2) R48.2(N2) R49.1
UNNAMED_9_CAP_I1401_N1: C65.1 L4.2(N2) L7.1
UNNAMED_9_CAP_I1416_N2: C114.2(N2) R47.1
UNNAMED_9_CAP_I1449_N1: C69.1 R46.2(N2)
UNNAMED_9_DIOLED_I1180_N: D3.C R113.1
UNNAMED_9_RES_I987_N2: Q14.3 R113.2(N2)
UNNAMED_10_AD7291_I1_AS0: R65.2(N2) R66.1 U24.11
UNNAMED_10_AD7291_I1_AS1: R63.2(N2) R64.1 U24.13
UNNAMED_10_AD7291_I1_DCAP: C133.1 U24.8
UNNAMED_10_AD7291_I1_VIN3: R67.2(N2) R68.1 U24.1
UNNAMED_10_AD7291_I1_VIN6: R61.2(N2) R62.1 U24.4
UNNAMED_10_AD7291_I1_VREF: C158.1 U24.7(VREF)
UNNAMED_10_ADG772_I53_D1: C216.1 U5.2
UNNAMED_10_ADG772_I53_IN1: Q6.3 R33.2(N2) U5.4
UNNAMED_10_ADG772_I53_S1A: C62.2(N2) U5.1
UNNAMED_10_ADG772_I53_S1B: U5.3 Y4.3
UNNAMED_10_ADM7160_I65_VOUT: C5.1 C113.1 R55.1 U7.5(VOUT) Y4.4(VDD)
UNNAMED_10_RES_I39_N2: R54.2(N2) R55.2(N2) Y4.1
UNNAMED_13_CN100PODDEVEN_I16_N4: JP3.2(COM) JX3.58
UNNAMED_13_CN100PODDEVEN_I16_N5: JP4.2(COM) JX3.60
UNNAMED_13_CN100PODDEVEN_I17_N4: JP1.2(COM) JX3.57
UNNAMED_13_CN100PODDEVEN_I17_N5: JP2.2(COM) JX3.59
USB_ID: JX3.63 U15.23
USB_OTG_CPEN: JX3.70 U15.17
USB_OTG_N: JX3.69 U15.19 U16.6
USB_OTG_P: JX3.67 U15.18 U16.1
USB_VBUS_OTG: JX3.68(N9) U15.22
V_0_N: JX3.3 U1.K9
V_0_P: JX3.1 U1.L10
VTT_0P75: C79.1 C80.1 C101.1 R136.2(N2) R137.2(N2) R138.2(N2) R139.2(N2) R140.2(N2) R141.2(N2) R143.2(N2) R144.2(N2) R145.2(N2) R146.2(N2) R147.2(N2) R148.2(N2) R149.2(N2) R150.2(N2) R151.2(N2) R152.2(N2) R153.2(N2) R154.2(N2) R155.2(N2) R156.2(N2) R159.2(N2) R160.2(N2) R161.1 R162.2(N2) R163.2(N2) U14.3 U24.2
VTTVREF: C76.1 C77.1 C81.1 C84.1 C102.1 C103.1 C122.2(N2) C123.2(N2) U1.H6 U1.P6 U2.H1 U2.M8 U3.H1 U3.M8 U14.6 U24.3
XTAL_N: C165.1 C216.2(N2) U17.M12

Pads without a net: JX1 9 10 11 12 13 14 17 18 19 20 23 24 25 26 29 30 31 32 35 36 37 38 41 42 43 44 47 48 49 50 53 54 55 56 61 62 63 64 67 68 69 70 73 74 75 76 78 79 80 81 82 83 84 87 88 89 90 91 92 93 94 97 99; JX2 1 2 3 4 5 6 7 8 13 14 20 23 24 25 26 29 30 31 32 68 70 73 74 75 76 81 82 83 84 87 88 89 90 93 94 95 96 97 99 100; JX3 2 4 5 7 8 9 10 11 13 14 15 16 19 20 21 22 25 26 27 28 30 31 32 33 42 44 64 66 73 74 75 76 79 80 81 82 85 86 87 88 91 92 93 94 97 98 99 100; JX4 13 14 15 16 81 82; U2 J1 J9 L1 L9 M7; U3 J1 J9 L1 L9 M7; U4 5; U6 4; U7 4; U9 4; U10 9 12 29 31 32; U13 A2 A3 A5 B1 B5 C1 C3 C5 D1 D5 E1 E2 E3 E4 E5; U15 12 15 16 25; U16 3 4; U17 A3 M3 M11; U19 8; U20 8; U21 5; U24 12

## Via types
v1: diameter 0.381, hole 0.203, TOP to BOTTOM, 1838 vias
v2: diameter 0.508, hole 0.254, TOP to BOTTOM, 410 vias

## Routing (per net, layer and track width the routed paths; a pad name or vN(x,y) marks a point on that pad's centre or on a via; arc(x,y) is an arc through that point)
1.0V:
  vias: v1(36.88,13.89) v1(36.88,13.38) v1(37.9,13.82) v1(37.9,13.32) v2(10.97,2.27) v2(10.97,1.51) v2(11.23,3.16) v2(11.48,1) v2(11.61,2.01) v2(11.99,2.65) v2(11.99,1.51) v2(56.95,1.63) v2(57.71,4.05) v2(57.84,3.03) v2(57.84,1.63) v2(58.18,4.59)
1.8V: length 16.9
  TOP w0.305: R22.2 75.87,4.55 77.52,6.2
  TOP w0.356: U19.1 78.96,6.23 v1(78.98,6.2)
  TOP w0.381: U19.16 77.48,8.02 v1(77.14,8.36) 77.45,8.67 U19.15 ; v1(86.92,7.73) 87.22,8.02 U20.16 ; v1(86.92,8.49) 87.1,8.67 U20.15 ; U20.1 88.61,6.75 v1(88.19,6.33) ; U20.3 v1(89.91,6.26) ; U20.2 89.26,6.51 v1(89.08,6.33) ; v1(79.61,6.08) U19.2 ; U19.3 v1(80.26,6.08)
  TOP w0.406: U20.4 v1(90.56,6.29) ; v2(80.95,6.08) 80.91,6.12 U19.4
  TOP w0.508: E9.1 v1(14.4,12.3)
  BOTTOM w0.254: R39.1 v2(63.87,2.01)
  vias: v1(11.99,10.78) v1(12.63,10.78) v1(13.9,11.79) v1(13.9,10.9) v1(14.4,11.79) v1(14.4,10.9) v1(15.04,11.41) v1(29.77,5.32) v1(30.41,5.06) v1(59.11,12.55) v1(59.36,13.19) v1(59.62,12.55) v1(59.87,13.19) v1(60.12,12.55) v1(60.38,13.19) v1(60.63,12.55)
1.35V: length 46.3
  TOP w0.508: v1(51.61,4.68) 51.61,3.35 E2.1 ; R35.2 v2(75.62,2.27)
  L3_SIGNAL w0.635: v2(64.06,15.09) 64.65,15.09 65.08,14.67 65.08,5.95 64.82,5.7 64.82,3.16 65.33,2.65 69.39,2.65 70.28,1.76 75.11,1.76 v2(75.62,2.27)
  L4_SIGNAL w0.635: v1(51.61,4.68) 51.61,5.82 52.63,6.84 57.96,6.84 64.06,12.94 v2(64.06,14.33) v2(64.06,15.09) v2(64.06,15.86)
  vias: v2(63.3,15.86) v2(63.3,15.09)
3.3V: length 35.6
  TOP w0.305: U5.6 79.32,57.91 79.55,58.15 80.32,58.15 80.57,58.4
  TOP w0.356: R43.1 v1(30.66,7.86)
  TOP w0.381: E8.1 32.69,58.59 v1(32.69,57.89) 32.69,57.04 D3.A
  TOP w0.406: R44.1 79.81,49 v1(79.55,49.26) 79.3,49.51 R42.1 ; C188.2 v1(77.01,58.91) ; C111.2 v1(73.33,46.21) ; v2(80.57,59.29) v2(81.21,59.29)
  TOP w0.508: E7.1 v1(26.47,59.54) ; v1(10.34,18.27) v1(11.1,18.27) 12.56,18.27 E15.1 ; E16.1 15.93,15.28 v1(15.93,15.98) ; v2(80.57,59.29) R33.1
  BOTTOM w0.254: U6.5 77.28,57.14 v1(76.76,56.62) ; v1(77.01,58.91) 77.28,58.64 U6.8
  BOTTOM w0.305: U24.10 73.6,45.94 v1(73.33,46.21) ; 5.51,26.97 4.96,26.42 U21.8 ; 5.51,26.97 v1(5.51,27.03) ; 5.51,26.97 C244.2 5.96,27.35 v1(6.28,27.03) ; v1(72.82,43.29) 73.33,42.78 73.33,41.95 R61.1
  BOTTOM w0.33: U24.17 78.68,45.44 78.81,45.57 v1(78.81,45.94) U24.16
  BOTTOM w0.406: v1(73.33,46.21) 72.79,46.21 C124.1 ; R65.1 74.54,48.05 v1(74.28,47.8) ; R63.1 v1(77.27,48.24) ; C199.1 75.96,58.91 v1(77.01,58.91) ; U7.1 76.19,53.13 75.71,52.66 v2(75.36,52.66) 74.86,53.17 C152.1 74.88,55.03 U7.3 ; v1(79.55,49.26) 78.88,49.26 C134.1
  vias: v2(35.8,53.96) v2(36.5,53.96)
GND: length 618.4
  TOP w0.127: 66.23,7.13 U4.22 66.23,7.49 66.47,7.73 ; 23.93,34.19 U1.U6 ; 68.46,24.89 v1(68.4,24.89)
  TOP w0.152: R29.1 26.98,8.11 R38.2
  TOP w0.254: v1(66.8,25.69) U17.H2 ; U1.E10 v1(33.94,31.39) ; U1.R8 v1(25.14,32.99) ; C109.2 49.7,38.65 v1(49.63,38.73) ; v1(49.63,18.77) 49.7,18.84 C95.2 ; U1.R12 v1(25.14,28.99) ; U1.J8 v1(30.74,32.99) ; U1.T3 v1(24.34,36.99) ; v1(69.2,33.69) U17.L11 ; U1.T13 v1(24.34,28.19) ; U1.V19 v1(22.74,23.39) ; v1(60.4,28.89) U17.A6 ; U17.A12 v1(60.4,34.49) ; v1(36.34,38.59) U1.B1 ; U17.F7 v1(64.4,30.49) ; v1(21.14,26.59) U1.Y15 ; v1(62.8,24.89) U17.D1 ; C92.2 49.72,29.25 v1(49.63,29.17) ; C118.2 42.34,38.02 v1(42.43,37.93) ; v1(69.2,30.49) U17.L7 ; U1.G10 v1(32.34,31.39) ; U1.C9 v1(35.54,32.19) ; v1(38.71,48.17) 39.08,47.8 39.36,47.8 C120.2 ; U17.C10 v1(62,32.89) ; U1.P13 v1(25.94,28.19) ; v1(69.2,34.49) U17.L12 ; v1(69.2,32.09) U17.L9 ; v1(64.4,26.49) U17.F3 ; v1(23.53,34.59) 23.93,34.19 ; U1.P7 v1(25.94,33.79) ; U1.M1 v1(27.54,38.59) ; U1.P17 v1(25.94,24.99) ; U1.D17 v1(34.74,24.99) ; U1.L8 v1(28.34,32.99) ; U17.C9 v1(62,32.09) ; C97.2 42.35,18.84 v1(42.43,18.77) ; v1(57.08,31.99) 56.94,32.12 U22.7 ; U1.G16 v1(32.34,25.79) ; U1.N8 v1(26.74,32.99) ; U1.N10 v1(26.74,31.39) ; v1(60.4,25.69) U17.A2 ; v1(62,33.69) U17.C11 ; v1(66.8,32.89) U17.H10 ; v1(48.83,39.53) 48.62,39.73 C116.2 ; v1(60.4,27.29) U17.A4 ; U1.H9 v1(31.54,32.19) ; v1(42.43,21.17) 42.34,21.25 C96.2 ; U1.K7 v1(29.94,33.79) ; v1(68.4,25.69) U17.K2 ; 21.81,8.58 U18.8 ; 21.13,8.87 v1(21.77,8.87) ; C91.2 49.52,17.86 v1(49.63,17.97) ; v1(42.43,39.53) 42.29,39.67 C102.2 ; U1.J12 v1(30.74,28.99) ; U1.R20 v1(25.14,22.59) ; U1.H13 v1(31.54,28.19) ; v1(36.34,29.79) U1.B11 ; v1(76.51,57.39) 76.63,57.51 U5.10 ; v1(66.8,26.49) U17.H3 ; v1(62.8,34.49) U17.D12 ; U1.F3 v1(33.14,36.99) ; U1.H7 v1(31.54,33.79) ; U1.N12 v1(26.74,28.99) ; U17.C8 v1(62,31.29) ; U1.K11 v1(29.94,29.79) ; U17.C7 v1(62,30.49) ; U1.A18 v1(37.14,24.19) ; v1(62,27.29) U17.C4 ; U1.J2 v1(30.74,37.79) ; U1.V9 v1(22.74,32.19) ; v1(62,34.49) U17.C12 ; C112.2 49.68,35.48 v1(49.63,35.53) ; v1(70,28.89) U17.M6 ; U1.N14 v1(26.74,27.39) ; v1(49.63,44.25) 49.32,44.56 C122.1 ; v1(69.2,32.89) U17.L10 ; v1(69.2,26.49) U17.L3 ; U1.Y5 v1(21.14,35.39) ; v1(66.8,30.49) U17.H7 ; v1(21.94,28.99) U1.W12 ; C123.1 49.39,27.33 v1(49.63,27.57) 50.41,26.78 C87.2 ; v1(42.43,35.53) 42.35,35.6 C115.2 ; U1.M7 v1(27.54,33.79) ; v1(62,25.69) U17.C2 ; C344.2 v1(85.24,9.63) ; v1(66.8,28.89) U17.H6 ; U1.L12 v1(28.34,28.99) ; U22.9 55.88,32.48 56.38,31.99 v1(56.44,31.99) 56.44,31.99 U22.8 ; U1.C4 v1(35.54,36.19) ; U1.P9 v1(25.94,32.19) ; v1(43.23,41.93) 43.23,41.92 C117.2 ; v1(60.4,28.09) U17.A5 ; U1.W2 v1(21.94,37.79) ; v1(61.2,24.89) U17.B1 ; U17.F9 v1(64.4,32.09) ; v1(70,27.29) U17.M4 ; U17.G12 v1(66,34.49) ; U1.K13 v1(29.94,28.19) ; U1.H11 v1(31.54,29.79) ; U1.U16 v1(23.54,25.79) ; U13.B3 68.23,56.62 v1(68.12,56.73) ; v1(61.2,25.69) U17.B2 ; v1(62,24.89) U17.C1 ; U17.K1 v1(68.4,24.89) ; v1(68.4,34.49) U17.K12 ; v1(60.4,24.89) U17.A1 ; v1(27.54,28.19) U1.M13 ; U1.K5 v1(29.94,35.39) ; v1(49.63,22.77) 49.64,22.78 C94.2 ; v1(69.2,31.29) U17.L8 ; U17.F11 v1(64.4,33.69) ; v1(42.43,22.77) 42.29,22.9 C103.2 ; U1.N4 v1(26.74,36.19) ; C343.2 v1(85.24,10.4) ; v1(61.2,34.49) U17.B12 ; v1(69.2,25.69) U17.L2 ; U1.G12 v1(32.34,28.99) ; U1.E20 v1(33.94,22.59) ; U1.P11 v1(25.94,29.79) ; U1.H19 v1(31.54,23.39) ; v1(64.4,24.89) U17.F1 ; v1(27.54,29.79) U1.M11 ; U1.K15 v1(29.94,26.59) ; U1.L18 v1(28.34,24.19) ; U1.T7 v1(24.34,33.79) ; v1(63.6,24.89) U17.E1 ; v1(67.6,25.69) U17.J2 ; U17.L1 v1(69.2,24.89) ; U1.C14 v1(35.54,27.39) ; U1.F10 v1(33.14,31.39) ; U1.F7 v1(33.14,33.79) ; U1.A8 v1(37.14,32.99)
  TOP w0.267: v1(72.44,25.95) arc(72.38,25.99) 72.32,26.02
  TOP w0.305: C196.2 v1(19.56,59.21) ; C196.2 v1(20,59.51) ; C196.2 v1(20,58.92) ; C13.1 v1(63.62,22.9) ; v2(42.34,52.94) 42.34,52.94 U9.6 ; v1(74.35,52.94) 74.22,52.81 C113.2 ; v1(45.14,60.79) 45.11,60.81 44.38,60.81 44.12,60.56 C81.2 44.06,60.5 43.36,61.2 v1(42.98,61.2) ; U18.6 23.11,8.62 v1(23.04,8.87) ; C315.2 v2(75.74,9.38) 75.74,9.89 76,10.14 C314.2 ; v1(22.4,8.87) 22.46,8.62 U18.7 ; 47.68,4.05 48.19,4.05 v1(48.31,4.17) ; C225.2 v1(29.77,11.41) ; C246.2 54.66,28.43 v1(54.41,28.18) ; 72.32,26.02 70.32,26.95 v1(70,27.29) ; C245.2 v1(58.47,28.68) ; 76.12,29.09 75.81,29.64 ; C311.2 v1(84.13,10.65) ; U18.5 23.76,8.55 v1(23.67,8.87) ; v2(65.71,3.54) 65.26,3.08 65.26,2.8 65.23,2.78 U4.1 ; U9.3 36.88,52.94 v2(36.56,52.81) ; v1(43.42,49.57) 43.49,49.51 R133.2 ; v1(60,22.4) 60,21.83 C12.1 60.5,21.95 v1(60.5,22.4) ; C79.2 49.84,58.4 49.35,57.91 v1(48.72,57.91) ; v2(6.79,17.77) 7.05,17.52 U11.11 7.05,15.34 U11.PAD 8.55,13.84 U11.2 ; C188.1 v1(75.81,59.61) ; v1(21.77,8.87) 21.81,8.58
  TOP w0.381: C72.2 v1(39.93,20.3) ; C79.2 49.14,58.78 v1(48.88,58.78) ; v1(10.63,15.96) 11.08,15.96 C54.2 ; C340.2 92.33,8.68 v1(92.33,8.67) U20.6 ; v1(29.9,5.95) 29.9,6.46 C224.2 ; C159.2 40.57,36.3 v1(39.93,36.3) ; v1(79.94,9.13) 80.39,8.67 U19.6 ; C10.2 v1(42.6,33.89) ; R29.1 25.2,9.89 v1(24.44,9.89) ; C107.2 v1(45.65,38.59) ; v1(91.24,12.17) 91.24,12.41 91.89,13.06 C341.2 ; C163.2 v1(42.6,32.11)
  TOP w0.508: Y2.4 v1(32.13,14.91) ; v2(69.9,46.46) 70.58,46.46 C111.1 ; C183.2 26.25,57.39 v2(26.28,57.36) ; J3.GND3 15.95,29.6 15.67,29.32 v1(14.85,29.32) ; M1.GND11 M1.GND12 63.03,17.15 ; v1(28.37,43.92) 29.05,43.25 C71.2 29.61,43.25 v1(30.28,43.92) ; v1(58.47,21.44) v1(58.47,18.65) ; v1(50.76,4.46) 50.79,4.49 C139.2 ; C49.2 R50.2 v2(17.58,14.78) ; v2(41.58,57.51) 42.31,56.79 C36.2 ; v1(19.19,14.93) 19.23,14.89 C211.2 ; v2(74.22,7.09) 73.84,7.09 73.2,6.46 C45.2 73.14,6.27 73.48,5.93 74.2,5.93 v2(74.22,5.95) ; v1(33.45,49.64) 33.45,50.48 Q14.2 ; v1(94.99,25.05) RXA.3 v1(97.97,25.05) ; C135.2 55.11,13.76 54.66,14.21 v2(53.27,14.21) 53.27,12.17 53.77,11.67 C137.2 ; U16.5 v2(15.55,51.04) ; SW1.2B v1(36.12,2.27) ; v1(45.65,17.89) 46.15,17.89 C88.2 ; R34.2 v2(77.4,1.12) ; R165.2 51.94,28.25 v1(52.47,28.25) ; C149.2 81.21,3.41 v1(81.97,3.41) ; C58.2 28.67,13.82 C63.2 26.72,13.7 v1(26.21,13.7) 25.45,13.7 C217.2 25.2,13.7 v1(24.69,13.7) 23.93,13.7 C73.2 23.67,13.7 v1(23.17,13.7) 22.4,13.7 C218.2 ; v2(2.21,34.53) 2.98,33.76 J3.GND4 ; v1(53.27,34.66) M1.GND7 v1(53.27,36.93) ; v1(54.41,25.76) C2.2 v1(57.08,25.76) ; v1(27.61,11.83) 27.61,11.27 27.11,10.78 C50.2 ; v1(72.23,48.43) C5.2 ; 34.72,18.52 v1(35.36,18.52) ; C150.2 v2(59.11,2.9) ; M1.GND13 v2(66.85,17.15) ; C313.2 77.52,15.09 77.46,15.16 v1(77.46,15.35) ; v1(53.27,27.53) M1.GND9 v1(53.27,25.26) ; v2(55.28,5.17) 55.46,5.35 C191.2 ; Y1.2 48.45,7.49 v1(48.82,7.86) ; 36.25,18.52 v1(36.88,18.52) ; v1(53.27,22.84) M1.GND10 v1(53.27,20.56) ; v2(43.36,2.01) 43.49,2.14 C138.2 ; C106.2 v1(45.65,41) ; 30.15,18.52 v1(30.79,18.52) ; SW1.2A v1(39.93,2.27) ; C1.2 21.77,15.73 v1(20.75,16.75) ; C201.2 20.75,14.21 v1(21.01,14.46) ; J3.GND2 16.05,22.21 v1(16.82,21.44) ; v1(97.97,28) RXA.2 v1(94.97,28) ; C65.2 74.79,11.87 v2(74.79,10.52) ; v2(11.1,37.57) 11.67,37.57 12.56,36.68 C29.2 v2(11.1,36.49) ; v2(58.2,59.37) 57.44,59.37 57.06,58.99 ; v2(10.85,16.87) 11.36,16.36 C54.2 C55.2 ; 57.06,58.99 57.06,58.36 57.31,58.1 v2(58.2,58.1) ; 57.06,58.99 57.08,58.97 C100.2 ; v1(97.79,39.43) TXA.2 v1(94.99,39.43) ; v1(4.5,22.33) 3.75,21.59 J3.GND1 3.01,21.15 3.01,22.03 v1(2.68,22.36) ; Y3.2 16.72,56.21 v1(15.74,57.19) ; C144.1 v2(75.36,3.41) ; C89.2 v1(46.53,23.6) ; v1(33.58,12.68) 34.3,11.96 Y2.2 ; v1(81.94,4.6) 81.26,4.6 C148.2 ; C203.2 16.07,10.9 v1(16.05,10.92) ; C53.2 v1(34.72,43.03) ; Q3.2 39.98,8.69 v1(39.13,9.54) ; v1(13.77,2.33) 13.51,2.08 13.51,1.72 C78.2 ; C193.2 52.12,1.25 v2(52.25,1.12) ; C108.2 v1(45.65,36.18) ; C175.2 v1(27.36,43.03) ; R13.2 v1(32.31,8.36) ; C86.2 v1(46.66,21.06) ; C178.2 v1(39.17,45.07) ; R26.2 v1(40.06,25.51) ; M1.GND4 v1(60.25,44.22) ; v2(59.11,4.17) 59.49,4.17 59.62,4.3 60,4.3 C142.1 60.44,4.74 C37.2 v2(60.44,8.3) 60.19,8.55 C64.2 ; v1(94.99,36.48) TXA.3 v1(97.97,36.48) ; v1(34.08,9.01) 34.09,9.01 34.09,8.41 Q1.2 ; M1.GND6 53.27,41.51 53.02,41.76 v1(52.25,41.76) R166.2 ; v1(57.5,44.22) M1.GND5 ; C197.2 v2(27.99,57.17) ; 31.68,18.52 v1(32.31,18.52) ; v2(11.66,9.89) 12.31,9.89 C119.2 ; 33.2,18.52 v1(33.83,18.52) ; v1(53.27,32.12) M1.GND8 v1(53.27,29.83) ; v1(25.58,0.74) 26.09,0.74 C61.2 ; S1.1 v2(3.1,7.81) ; R191.2 v1(44.5,13.32) ; 47.68,4.05 C39.2 ; R176.2 v1(19.23,49.26) ; C208.2 v1(19.1,9.25) ; v2(87.59,12.05) 87.09,12.55 87.07,12.55 86.92,12.7 86.92,12.72 C342.2 ; Q2.2 v2(12.6,58.88) ; C226.2 24.44,10.52 v1(24.44,9.89) ; C129.2 61.58,13.25 v2(61.53,13.2) ; C179.2 v1(24.69,43.03) ; C146.2 v2(59.23,1.25) ; 28.63,18.52 v1(29.26,18.52) ; S4.1 v1(45.04,53.48) ; 81.7,22.89 M1.GND16 ; C41.2 v1(7.16,9.25) ; v2(84.25,59.8) 84.61,59.44 Q6.2 ; C364.2 v1(53.65,2.01) ; E12.1 v2(27.42,51.61) ; Q4.2 v2(6.12,54.31) ; J3.6 v1(4.61,29.46) ; R14.2 v2(14.02,58.4) ; 72.19,44.22 M1.GND2
  BOTTOM w0.203: U14.4 48.31,59.02 48.55,58.78 v1(48.88,58.78) ; v1(48.06,41.13) 48.06,41.16 U3.J8 ; U3.E1 v1(42.43,37.93) ; U3.D8 v1(48.83,37.13) ; U3.G1 v1(42.43,39.53) ; U3.G8 v1(48.83,39.53) ; U3.T9 49.23,47.13 ; U3.E8 v1(48.83,37.93)
  BOTTOM w0.254: U6.PAD 79.55,57.64 U6.3 ; U24.6 74.87,43.94 v1(75.24,44.3) ; C330.2 65.96,34.53 v1(66,34.49) ; v1(42.43,37.93) 42.83,37.53 U3.D1 ; U3.E1 42.95,38.21 43.51,38.21 U3.E2 ; U3.G9 49.23,39.93 v1(48.83,39.53) ; C80.2 50.98,57.39 v1(50.85,57.26) ; v2(65.52,35.6) C355.2 C356.2 ; v1(21.14,35.39) 20.63,34.88 20.63,34.4 C169.2 ; U24.9 75.63,45.44 ; v1(35.87,14.71) 36.16,15.01 ; U14.8 U14.PAD
  BOTTOM w0.305: v1(73.08,40.88) 73.08,40.88 73.52,40.88 R62.2 ; C76.2 25.97,33.83 v1(25.94,33.79) ; JX3.71 v1(6.78,39.37) ; 64.73,5.47 65.01,5.19 65.58,5.19 v2(65.71,5.06) ; U2.F9 v1(48.83,22.77) ; v1(5.77,20.81) 5.96,20.62 C243.1 ; U21.4 3.01,22.03 v1(2.68,22.36) ; R68.2 v1(77.01,40.75) ; U6.PAD 79.05,57.64 U6.6 ; v1(31.54,33.79) 31.57,33.83 C77.2 ; R66.2 74.49,48.95 74.3,48.95 v1(73.97,48.62) ; C98.2 66.7,40.18 v1(67.43,40.18) ; C98.2 v1(66.35,40.81) ; C98.2 66.69,39.48 v1(67.43,39.48) ; v1(62,31.29) v1(62,30.49) ; C104.1 v1(57.84,36.43) ; R64.2 77.4,49 77.6,48.8 v1(77.6,48.75) ; C93.1 68.12,38.59 v1(68.25,38.72) ; v1(83.08,44.3) 82.95,44.17 JX4.18 ; U2.D8 v1(48.83,21.17) ; JX3.61 v1(6.83,35.37) ; C335.2 v1(64.19,37.83) ; 58.73,35.03 v1(58.09,35.03) ; C244.1 v1(6.47,27.98) ; C84.2 v1(45.26,57.64)
  BOTTOM w0.356: v1(62,25.69) 62.18,25.88 C334.2 ; U3.A9 v1(49.63,35.53) U3.B9 ; v1(64.4,24.89) 64.35,24.94 C322.2 63.64,24.94 v1(63.6,24.89) ; U2.J8 v1(48.83,25.17) ; v1(49.63,30.77) 49.23,30.37 U2.T9 ; U2.M9 v1(49.63,27.57) ; C319.2 v1(62,30.49) 61.49,29.99 C360.2 ; v1(62,32.89) 61.96,32.86 C321.2 61.96,32.12 v1(62,32.09) ; v1(49.63,44.25) 49.55,44.25 U3.M9 ; U2.P1 v1(42.43,29.17) ; R125.2 69.97,27.32 v1(70,27.29) ; U2.G9 v1(49.63,22.77) ; U3.M1 v1(42.43,44.33) ; v1(48.83,22.77) U2.G8 ; v1(67.6,25.69) 67.59,25.7 C326.2 ; v1(69.2,26.49) 69.01,26.68 C333.2 ; U2.E1 v1(42.43,21.17) ; U3.J2 v1(43.23,41.93) ; U3.P1 v1(42.43,45.93) ; v1(68.4,25.69) 68.39,25.7 C329.2 ; U2.A9 v1(49.63,17.97) ; 49.23,47.13 49.63,47.53 v1(49.63,47.53) ; U2.B1 v1(42.43,18.77) ; U2.B9 v1(49.63,18.77) ; C325.2 60.38,28.91 v1(60.4,28.89) ; U3.P9 v1(49.63,45.93) ; U2.B3 v1(44.83,19.57) ; U2.E8 v1(48.83,21.17) ; U2.P9 v1(49.63,29.17) ; U3.B1 v1(42.43,35.53) ; U2.J2 v1(43.23,24.37) ; U2.G1 v1(42.43,22.77) ; U3.T1 v1(42.43,47.53) ; U2.T1 v1(42.43,30.77) ; U3.F9 v1(49.63,38.73) ; U2.M1 v1(42.43,27.57) ; U2.E2 v1(43.23,21.17)
  BOTTOM w0.381: v1(82.96,12.97) JX4.96 ; v1(80.29,35.36) 81.54,35.36 JX4.40 ; R5.2 71.93,57.13 v1(71.68,56.88) ; JX4.84 82.75,17.77 82.98,17.54 v1(82.98,17.32) ; C214.2 14.15,7.86 v1(14.15,8.24) ; JX3.12 11.54,15.37 10.95,15.96 v1(10.63,15.96) ; v1(87.3,44.49) 87.3,44.3 87.17,44.17 JX4.17 ; C43.1 46.53,61.2 v2(46.92,60.81) ; JX4.72 v1(80.19,22.57) ; v1(83.03,41.36) 83.03,41.54 82.8,41.77 JX4.24 ; JX4.30 v1(82.88,39.37) ; v1(87.54,35) 87.17,35.37 JX4.39 ; C165.2 v1(72.26,35.11) ; U2.D1 v1(43.23,21.17) ; v1(80.19,31.37) JX4.50 ; v1(80.16,15.37) JX4.90
  BOTTOM w0.406: v1(80.16,23.73) 80.16,24.77 80.36,24.97 JX4.66 ; v1(87.75,29) 87.72,28.97 JX4.55 ; JX4.56 81.6,29.03 82.65,29.03 v1(82.87,29.24) ; C323.2 70.47,22.47 v2(70.47,22.98) 70.47,23.53 C320.2 ; JX4.49 v1(84.62,31.37) ; v2(10.85,16.87) 10.85,17.35 11.26,17.77 JX3.18 ; R135.2 v1(34.6,43.8)
  BOTTOM w0.508: v1(9.58,46.57) JX3.89 ; JX1.46 v2(48.73,53.99) JX1.45 ; C132.2 C136.2 67.17,14.01 v2(66.09,12.94) 64.95,12.94 64.73,12.72 JX2.85 ; v2(6.91,6.33) C128.2 C130.2 C131.2 6.66,1.51 v2(6.28,1.12) ; v2(36.56,52.81) 36.73,52.65 JX1.16 ; v2(41.58,57.51) 41.53,57.46 JX1.27 ; v2(58.2,58.1) 57.77,58.53 C82.2 ; R41.2 48.31,2.9 v1(48.31,4.17) ; 31.68,18.52 v1(32.31,18.52) ; JX1.95 v2(68.73,53.92) ; JX4.12 82.84,46.57 v2(83.75,47.48) 84.65,46.57 JX4.11 ; v1(20.75,16.75) 21.22,16.75 C60.2 ; R50.2 v2(17.58,14.78) ; JX4.6 v2(82.95,48.97) ; JX3.55 v2(6.81,32.97) ; JX1.34 v2(43.93,52.49) ; C83.2 56.88,60.31 v1(57.58,60.31) ; 65.71,3.47 v2(65.71,3.54) ; v2(9.45,44.17) JX3.83 ; v1(76.89,43.92) 76.76,44.3 U24.PAD v1(75.74,45.32) 75.24,45.83 v1(75.24,45.96) ; 25.45,18.52 v1(24.56,18.52) 23.93,18.52 ; U3.B3 45.4,35.93 v1(45.65,36.18) ; JX2.71 v1(59.13,9.25) JX2.72 ; C34.2 43.7,2.36 v2(43.36,2.01) ; v1(78.92,56.62) 78.92,56.75 U6.PAD ; C32.2 24.18,46.37 v2(24.18,45.57) ; C101.2 52.63,49 v1(53.14,49) ; v2(46.92,60.81) v1(46.92,59.54) U14.PAD ; C75.2 30.28,2.14 v1(30.79,2.14) ; U7.2 v2(78.03,54.08) ; 20.88,18.52 v1(21.52,18.52) ; C324.2 67.04,23.6 67.04,23.35 67.36,23.03 v2(67.36,22.84) 67.36,22.71 67.04,22.4 67.04,22.14 C328.2 ; v2(87.59,12.05) 87.56,12.08 87.56,12.68 87.27,12.97 JX4.95 ; JX2.21 v1(39.13,9.54) 39.29,9.38 41.07,9.38 41.53,9.83 JX2.27 ; JX2.16 v1(36.73,8.08) ; JX2.33 v1(43.93,9.74) ; JX1.85 v2(64.73,52.43) JX1.86 ; R119.2 v2(70.28,57.64) ; JX2.52 51.13,4.97 51.07,4.91 51.07,4.77 v1(50.76,4.46) C365.2 ; JX3.78 v2(11.1,41.77) ; C125.2 v1(36.76,43.03) ; v1(10.98,20.17) JX3.24 ; C219.2 15.89,15.06 v2(16.82,15.98) ; JX1.66 v1(56.73,52.53) ; R116.2 v2(59.36,59.29) ; v2(19.48,55.23) 20.33,55.23 C184.2 ; C332.2 v1(62.28,38.59) ; C251.2 v1(37.52,49.26) ; v2(55.28,5.17) 56.42,5.17 56.73,5.48 JX2.66 ; JX2.92 v2(67.13,8.11) ; C212.2 v1(29.77,2.9) ; v1(87.36,18.33) 87.36,17.77 JX4.83 ; JX3.23 8.14,20.17 7.04,20.17 6.66,19.79 v2(6.66,19.41) ; v1(18.85,44.94) C27.2 v1(20.25,43.67) ; v1(82.96,26.75) 82.78,26.57 JX4.62 ; v1(25.94,29.79) 25.33,30.4 C48.2 ; C22.2 v1(17.58,24.87) ; v2(59.11,4.17) 59.11,4.05 59.36,3.79 C69.2 C67.2 ; 22.4,18.52 v1(23.04,18.52) ; v1(29.26,18.52) 27.1,18.52 ; JX2.65 56.69,10.92 v1(56.69,8.87) ; v1(78.67,51.54) 78.54,51.42 C134.2 ; C24.1 62.41,41.64 ; 62.41,41.64 v2(64.06,41.64) ; 62.41,41.64 v2(60.63,41.64) ; JX2.46 48.73,7.76 v1(48.82,7.86) ; JX4.29 v1(87.28,39.37) ; 33.2,18.52 v1(33.83,18.52) ; JX3.50 v1(10.97,30.57) ; C331.2 v1(56.44,27.54) ; v2(69.01,43.16) 69.81,43.16 C158.2 ; JX1.33 v2(43.93,54.02) ; JX3.65 v1(6.82,36.97) ; JX1.72 v1(59.13,52.54) ; C181.2 v2(23.59,53.92) ; JX4.71 v2(87.33,22.57) ; C59.2 v1(19.19,14.93) ; JX1.15 36.73,56.98 v2(36.76,57) ; C40.2 v1(63.55,47.61) ; v2(73.08,58.91) 73.71,58.91 73.97,58.66 C199.2 ; v1(38.41,4.93) 38.7,4.93 39.13,5.37 JX2.22 ; 70.03,3.28 69.14,3.28 C68.2 68.76,4.05 68.51,4.3 v2(68.38,4.3) ; v1(62.66,58.4) 63.3,59.04 R120.2 ; JX2.15 v1(36.73,12.15) ; JX1.39 v2(46.33,54) ; C105.1 v1(59.23,38.72) ; v2(4.5,15.6) 4.88,15.98 4.88,16.24 ; C145.1 v2(16.44,41) ; 34.72,18.52 v1(35.36,18.52) ; v2(52.25,1.12) C194.2 53.18,1.54 v1(53.65,2.01) ; v2(87.36,24.97) JX4.65 84.71,24.97 84.41,25.28 84.41,26.22 84.76,26.57 JX4.61 ; JX3.35 v2(9.61,24.97) ; v2(50.6,13.06) 51.13,12.53 JX2.51 ; JX3.56 v1(11.23,32.97) ; JX4.23 v1(87.33,41.77) ; JX2.45 48.73,9.03 v1(48.69,9) ; JX2.28 v1(41.53,5.13) ; v1(30.28,43.92) 29.61,43.25 C71.2 29.05,43.25 v1(28.37,43.92) ; JX2.77 v2(61.53,13.2) ; C133.2 v1(70.59,44.94) ; JX3.84 v2(11.1,44.17) ; JX3.6 v1(11.26,12.97) ; JX2.34 v1(43.93,4.36) ; v2(11.1,35.37) JX3.62 ; v2(11.12,39.37) JX3.72 ; v1(79.3,58.78) v2(79.3,59.54) ; C121.2 v1(34.72,43.03) ; C327.2 v1(60.25,37.83) ; JX1.52 v2(51.13,52.54) ; 37.77,18.52 v1(38.41,18.52) ; C57.2 v2(6.02,9.25) ; JX3.96 v1(11.1,48.97) ; JX1.28 41.53,52.12 v2(42.34,52.94) ; C200.2 v2(83.24,56.12) ; JX4.40 82.81,35.37 83.16,35.72 v1(83.16,36.51) ; C167.2 v1(17.58,26.52) ; C11.2 v1(32.06,43.03) ; C182.2 v2(21.3,46.5) ; C20.2 v1(23.29,43.03) ; C198.2 v1(17.03,18.99) ; C210.2 26.47,16.11 26.85,16.49 v2(27.1,16.49) ; C70.2 v1(39.93,20.3) ; C18.2 v1(17.58,23.48) ; JX1.40 v2(46.33,52.48) ; JX1.51 v2(51.13,53.98) ; 36.16,15.01 C195.2 ; JX3.77 v2(9.7,41.77) ; C162.2 v1(39.93,36.3) ; JX2.39 v1(46.33,8.49) JX2.40 ; JX2.86 64.73,5.47 ; C147.2 58.26,18.65 v1(58.47,18.65) ; v1(10.85,26.57) JX3.40 ; v2(16.44,1.82) 17.26,1.82 17.32,1.89 17.32,0.74 ; v1(76.51,57.39) 76.38,57.26 75.49,57.26 74.94,56.71 C152.2 ; JX1.77 v2(61.53,53.96) ; C170.2 18.59,30.46 v1(18.09,30.46) ; R12.1 14.09,2.33 v1(13.77,2.33) ; C358.2 v2(89.33,56.75) ; JX3.95 v1(9.58,48.97) ; 36.25,18.52 v1(36.88,18.52) ; 30.15,18.52 v1(30.79,18.52) ; JX1.96 v2(68.73,52.53) ; JX1.71 v1(59.13,53.98) ; v2(69.9,46.46) C124.2 ; JX1.22 39.13,52.43 ; JX3.29 v2(9.59,22.57) ; JX4.5 v2(84.54,48.97) ; v1(11.12,46.57) JX3.90 ; JX1.21 39.13,53.92 ; JX3.17 v2(6.79,17.77) ; JX3.49 v2(9.59,30.57) ; JX2.91 v2(67.13,9.38) ; C17.2 v1(25.96,43.03) ; v2(67.62,3.54) v2(67.62,4.3) ; C361.2 v2(89.33,58.4) ; C171.2 v1(17.58,34.14) ; C46.2 v1(17.58,28.05) ; JX1.65 v1(56.73,53.99) ; v2(87.38,15.37) JX4.89
  vias: v1(5.89,16.36) v1(6.78,49) v1(6.78,15.6) v1(6.78,14.84) v1(6.78,14.21) v1(6.78,13.57) v1(7.16,51.16) v1(14.78,21.57) v1(19.1,36.05) v1(19.61,59.93) v1(19.86,8.74) v1(19.86,8.24) v1(20.37,8.74) v1(20.37,8.24) v1(21.26,20.68) v1(21.77,7.35) v1(21.77,6.84) v1(21.77,6.33) v1(21.77,5.82) v1(21.77,5.32) v1(22.28,7.35) v1(22.28,6.84) v1(22.28,6.33) v1(22.28,5.82) v1(22.28,5.32) v1(22.79,7.35) v1(22.79,6.84) v1(22.79,6.33) v1(22.79,5.82) v1(22.79,5.32) v1(23.29,7.35) v1(23.29,6.84) v1(23.29,6.33) v1(23.29,5.82) v1(23.29,5.32) v1(23.8,7.35) v1(23.8,6.84) v1(23.8,6.33) v1(23.8,5.82) v1(23.8,5.32) v1(36.76,44.05) v1(38.15,43.92) v1(38.91,17.89) v1(39.68,17.89) v1(40.31,17.89) v1(45.52,23.6) v1(45.65,21.06) v1(46.66,59.93) v1(46.66,59.04) v1(47.17,59.93) v1(47.17,59.04) v1(47.55,14.84) v1(49.2,14.84) v1(53.01,17.76) v1(55.69,17.11) v1(56.44,31.1) v1(56.95,31.1) v1(59.23,30.21) v1(60,22.9) v1(60.5,22.9) v1(64.25,21.32) v1(64.63,20.05) v1(64.7,49.26) v1(66.09,18.46) v1(66.98,52.81) v1(67.43,17.89) v1(68.44,41.07) v1(68.44,17.95) v1(68.89,45.45) v1(69.39,37.45) v1(69.65,38.21) v1(69.78,38.97) v1(69.84,21.38) v1(69.84,20.87) v1(69.84,20.3) v1(70.09,17.89) v1(70.28,39.61) v1(70.35,21.38) v1(70.35,20.87) v1(70.35,20.3) v1(71.05,17.95) v1(71.55,40.62) v1(71.93,17.88) v1(72.44,40.88) v1(72.44,25.13) v1(72.76,21.57) v1(72.76,20.24) v1(72.76,17.88) v1(72.89,42.4) v1(73.01,38.08) v1(73.27,32.75) v1(73.27,25.89) v1(73.27,24.49) v1(73.33,31.05) v1(73.33,29.27) v1(73.33,28.66) v1(73.46,36.75) v1(73.52,21.57) v1(73.52,20.24) v1(73.52,17.88) v1(73.78,38.08) v1(73.94,42.17) v1(74.16,31.03) v1(74.16,30.59) v1(74.22,36.75) v1(74.25,32.72) v1(74.22,26) v1(74.47,43.29) v1(74.6,31.03) v1(74.6,30.59) v1(74.73,20.24) v1(74.86,21.95) v1(75.01,32.32) v1(75.04,17.88) v1(75.24,45.32) v1(75.26,37.24) v1(75.55,20.24) v1(75.74,45.96) v1(75.68,21.89) v1(75.81,17.88) v1(76.13,43.92) v1(76.25,45.96) v1(76.25,45.32) v1(76.19,32.3) v1(76.32,20.24) v1(76.57,27.22) v1(76.57,21.83) v1(76.58,29.86) v1(76.63,17.88) v1(76.76,45.96) v1(76.76,45.32) v1(77.14,34.75) v1(77.08,20.24) v1(77.27,45.96) v1(77.27,45.32) v1(77.27,44.3) v1(77.33,25.83) v1(77.46,25.13) v1(77.47,22.18) v1(77.46,17.88) v1(77.51,26.52) v1(77.65,43.03) v1(77.65,34.75) v1(77.71,32.3) v1(77.9,41.19) v1(77.97,27.79) v1(77.97,25.44) v1(77.9,20.24) v1(78.03,30.14) v1(78.16,39.67) v1(78.11,36.18) v1(78.11,35.47) v1(78.11,34.75) v1(78.47,36.81) v1(78.6,17.87) v1(78.86,30.14) v1(78.92,58.4) v1(78.98,38.46) v1(79.05,20.3) v1(79.11,32.3) v1(79.15,22.71) v1(79.17,17.87) v1(79.33,39.17) v1(79.3,23.35) v1(79.3,9.76) v1(79.3,9.13) v1(79.3,8.49) v1(79.43,43.35) v1(79.62,20.3) v1(79.68,30.08) v1(79.74,27.22) v1(79.81,58.78) v1(79.94,57.64) v1(79.94,9.76) v1(79.94,8.49) v1(80.13,30.65) v1(80.13,26.65) v1(80.19,39.53) v1(80.19,37.64) v1(80.19,32.3) v1(80.19,20.3) v1(80.57,9.76) v1(80.57,9.13) v1(80.57,8.49) v1(82.92,24.3) v1(83.19,33.28) v1(83.36,19.67) v1(83.49,39.2) v1(83.64,41.82) v1(83.62,17.06) v1(83.69,44.76) v1(83.75,26.97) v1(83.85,49.69) v1(83.81,29.64) v1(83.81,24.43) v1(83.9,33.59) v1(84,23.92) v1(84,23.22) v1(84,19.48) v1(84.2,39.2) v1(84.25,16.87) v1(84.28,45.17) v1(84.57,27.29) v1(84.51,24.62) v1(84.57,19.22) v1(84.62,42.53) v1(84.61,36.43) v1(84.61,33.89) v1(87.3,37.45) v1(87.49,33.13) v1(87.75,47.98) v1(87.81,44.88) v1(88.06,25.32) v1(88.06,15.6) v1(88.11,37.75) v1(88.25,18.08) v1(88.32,45.26) v1(88.32,35.26) v1(88.44,48.43) v1(88.44,33.45) v1(88.83,31.03) v1(88.83,29.32) v1(88.89,45.64) v1(88.89,25.32) v1(88.89,15.35) v1(88.95,9.63) v1(88.95,9) v1(88.95,8.36) v1(88.98,38.06) v1(89.08,27.73) v1(89.21,33.45) v1(89.33,49) v1(89.4,31.03) v1(89.49,35.72) v1(89.59,46.15) v1(89.65,17.63) v1(89.59,9.63) v1(89.59,9) v1(89.59,8.36) v1(89.71,25.32) v1(89.71,15.03) v1(89.97,33.45) v1(89.94,31.03) v1(90.03,27.73) v1(90.22,38.59) v1(90.22,9.63) v1(90.22,9) v1(90.22,8.36) v1(90.45,36.13) v1(90.54,25.32) v1(90.48,17.38) v1(90.54,14.78) v1(91.05,50.02) v1(91.05,47.16) v1(91.11,38.84) v1(91.21,36.38) v1(91.81,50.27) v1(91.81,47.67) v1(91.94,16.87) v1(91.94,14.27) v1(92,27.73) v1(92,25.32) v1(92.57,50.46) v1(92.57,47.92) v1(92.57,39.12) v1(92.57,36.75) v1(92.7,16.55) v1(92.7,14.08) v1(92.89,27.73) v1(92.89,25.32) v1(93.33,50.59) v1(93.33,48.11) v1(93.4,39.12) v1(93.4,36.75) v1(93.46,16.36) v1(93.46,13.95) v1(93.84,27.73) v1(93.84,25.32) v1(94.16,50.59) v1(94.16,48.18) v1(94.22,39.12) v1(94.22,36.75) v1(94.22,16.3) v1(94.22,13.89) v1(94.6,12.81) v1(94.98,50.59) v1(94.98,48.18) v1(94.98,47.42) v1(95.05,17.13) v1(95.02,16.3) v1(95.02,13.89) v1(95.43,40.3) v1(95.56,51.73) v1(95.49,12.81) v1(95.68,47.03) v1(96.25,12.81) v1(96.38,51.73) v1(96.45,47.03) v1(96.38,40.3) v1(97.08,12.81) v1(97.27,51.73) v1(97.33,47.03) v1(97.4,40.3) v1(97.87,50.59) v1(97.84,49.32) v1(97.87,48.11) v1(97.84,15.03) v1(97.84,13.63) v1(97.84,12.81) v1(97.92,16.57) v2(1.2,55.73) v2(1.2,54.46) v2(1.2,53.19) v2(1.2,51.92) v2(1.2,50.65) v2(1.2,49.38) v2(1.2,48.11) v2(1.2,46.84) v2(1.2,45.57) v2(1.2,44.3) v2(1.2,43.03) v2(1.2,41.76) v2(1.2,40.49) v2(1.2,39.22) v2(1.2,37.95) v2(1.2,36.68) v2(1.2,35.41) v2(1.2,34.14) v2(3.23,44.18) v2(3.86,36.68) v2(4.24,41) v2(4.37,54.08) v2(5.64,49.26) v2(7.55,60.81) v2(8.82,60.81) v2(9.32,55.1) v2(9.7,43.03) v2(10.09,60.81) v2(10.97,59.16) v2(11.36,60.81) v2(14.78,43.67) v2(15.29,60.43) v2(15.42,48.37) v2(15.55,55.99) v2(17.96,54.34) v2(18.72,22.59) v2(19.86,47.35) v2(19.99,50.4) v2(21.01,45.07) v2(21.39,53.96) v2(21.39,53.19) v2(21.39,52.56) v2(21.39,51.92) v2(21.39,42.78) v2(22.91,21.83) v2(23.42,52.05) v2(29.26,60.56) v2(33.71,53.7) v2(35.23,52.81) v2(35.87,60.18) v2(38.47,53.89) v2(38.47,53.32) v2(38.47,52.75) v2(39.04,53.89) v2(39.04,53.32) v2(39.04,52.75) v2(39.04,46.34) v2(39.3,60.56) v2(39.42,0.87) v2(39.61,53.89) v2(39.61,53.32) v2(39.61,52.75) v2(40.69,0.87) v2(41.96,0.87) v2(48.95,13.06) v2(52,31.1) v2(53.65,42.65) v2(54.03,46.97) v2(54.66,36.05) v2(55.17,38.59) v2(55.42,42.78) v2(56.69,38.08) v2(58.47,41.64) v2(58.6,26.4) v2(58.98,60.81) v2(58.98,46.84) v2(59.11,4.81) v2(59.74,5.06) v2(60.25,60.81) v2(60.38,5.06) v2(61.52,60.81) v2(62.79,60.81) v2(64.06,60.81) v2(65.33,60.81) v2(65.71,4.3) v2(66.47,9.38) v2(66.47,8.74) v2(66.47,8.11) v2(66.6,60.81) v2(66.73,5.06) v2(66.73,4.3) v2(66.73,3.54) v2(67.11,8.74) v2(67.62,5.06) v2(67.87,60.81) v2(68.38,5.06) v2(68.38,3.54) v2(69.14,60.81) v2(70.41,60.81) v2(71.68,60.81) v2(72.95,60.81) v2(74.22,60.81) v2(75.11,9.89) v2(75.11,9.13) v2(75.49,60.81) v2(76.76,60.81) v2(78.03,60.81) v2(78.67,1.12) v2(79.3,60.81) v2(79.94,1.12) v2(80.57,60.81) v2(81.21,1.12) v2(81.84,60.81) v2(82.48,1.12) v2(83.11,60.81) v2(83.75,1.12) v2(84.38,60.81) v2(85.02,1.12) v2(85.65,60.81) v2(86.29,1.12) v2(86.92,60.81) v2(87.43,4.81) v2(87.56,1.12) v2(87.94,55.48) v2(88.19,60.81) v2(88.83,1.12) v2(88.95,53.58) v2(89.46,60.81) v2(90.1,1.12) v2(90.22,42.65) v2(90.6,3.28) v2(90.73,60.81) v2(90.73,35.41) v2(91.37,1.12) v2(91.49,53.45) v2(91.75,59.04) v2(92,60.81) v2(92.13,56.12) v2(92.51,18.9) v2(92.64,45.07) v2(92.64,1.12) v2(92.84,33.71) v2(92.82,30.77) v2(93.27,60.81) v2(93.52,51.8) v2(93.52,11.92) v2(93.65,46.97) v2(93.65,43.8) v2(93.91,35.16) v2(94.29,20.94) v2(94.98,32.24) v2(95.3,41.64) v2(95.3,8.11) v2(95.81,11.79) v2(96.19,53.07) v2(96.7,43.8) v2(96.95,46.08) v2(98.1,34.78) v2(98.1,11.92) v2(98.22,19.41) v2(98.35,30.46) v2(98.35,23.48) v2(98.99,55.1) v2(98.99,53.83) v2(98.99,52.56) v2(98.99,51.29) v2(98.99,50.02) v2(98.99,48.75) v2(98.99,47.48) v2(98.99,46.21) v2(98.99,44.94) v2(98.99,43.67) v2(98.99,42.4) v2(98.99,41.13) v2(98.99,39.86) v2(98.99,38.59) v2(98.99,37.32) v2(98.99,36.05) v2(98.99,34.78) v2(98.99,33.51) v2(98.99,32.24) v2(98.99,30.97) v2(98.99,29.7) v2(98.99,28.43) v2(98.99,27.16) v2(98.99,25.89) v2(98.99,24.62) v2(98.99,23.35) v2(98.99,22.08) v2(98.99,20.81) v2(98.99,19.54) v2(98.99,18.27) v2(98.99,17) v2(98.99,15.73) v2(98.99,14.46) v2(98.99,13.19) v2(98.99,11.92) v2(98.99,10.65) v2(98.99,9.38) v2(98.99,8.11) v2(98.99,6.84) v2(98.99,5.57)
